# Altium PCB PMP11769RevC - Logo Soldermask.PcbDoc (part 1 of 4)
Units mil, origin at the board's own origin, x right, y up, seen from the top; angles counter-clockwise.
Board outline 7800 x 8510 mil, 4 copper layers (Top, Inner Top, Inner Bottom, Bottom), stack 33.235 mil thick; 451 components, 226 nets, 1199 pads, 1742 vias.
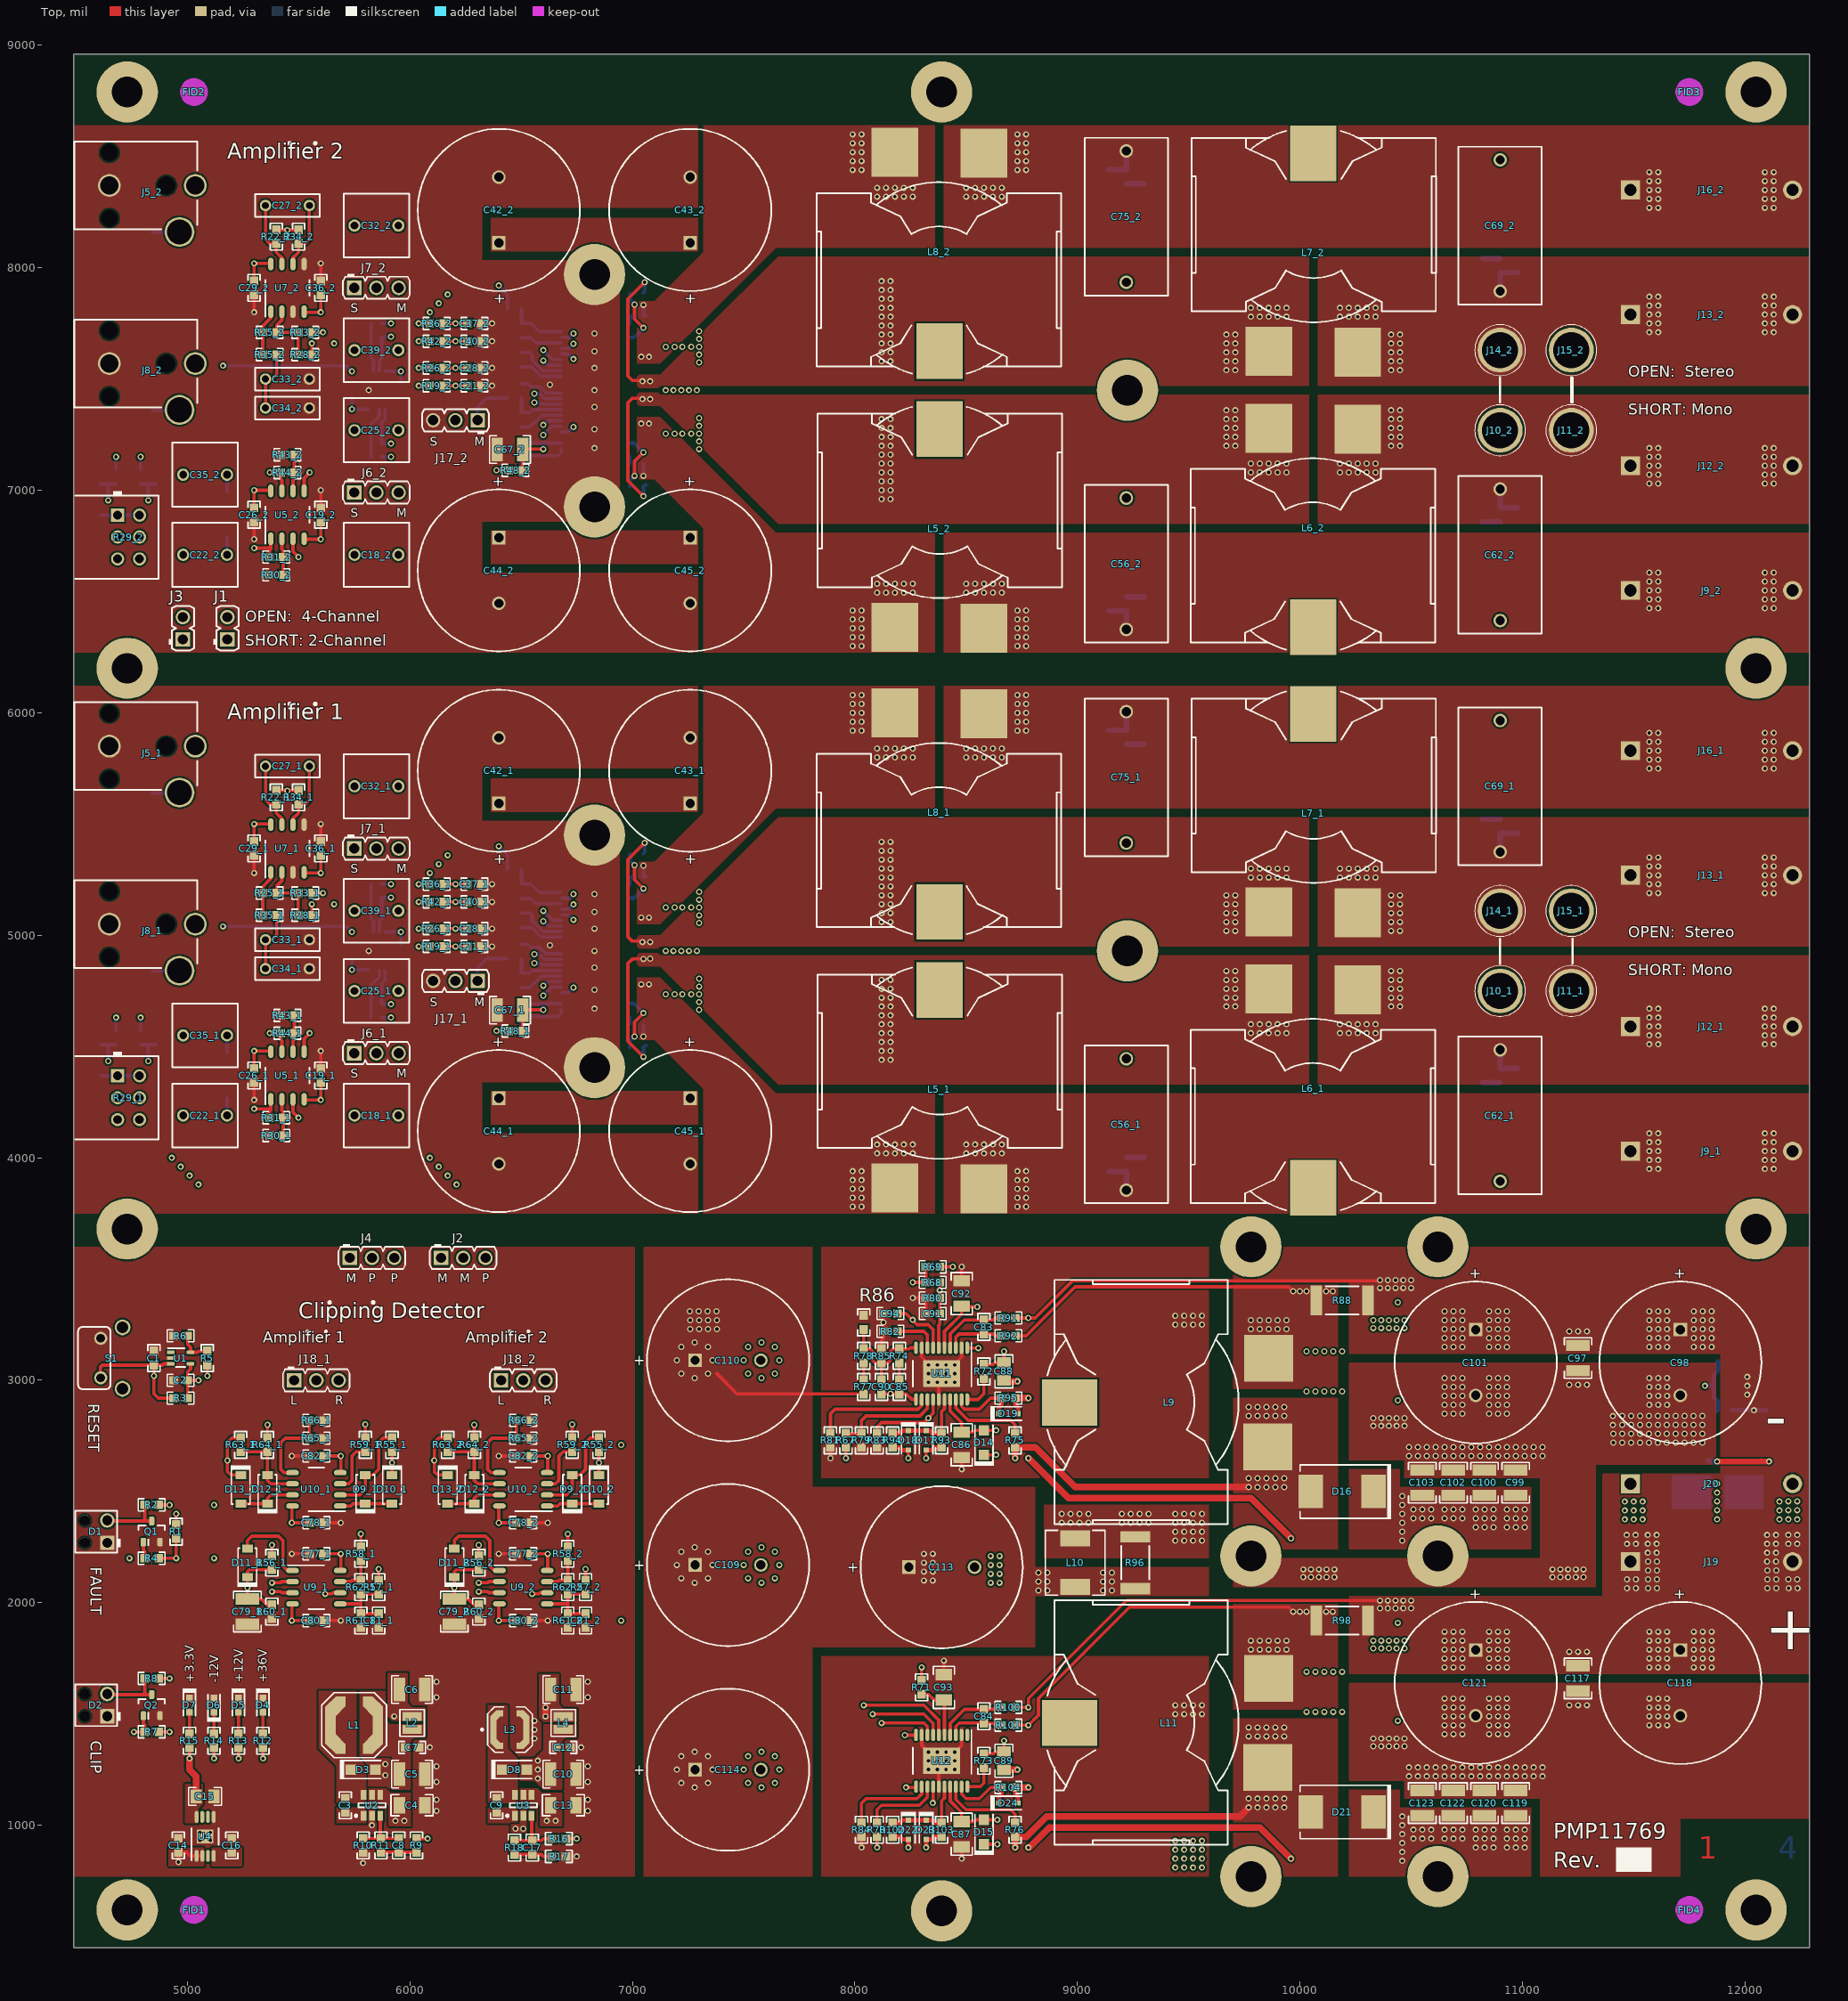
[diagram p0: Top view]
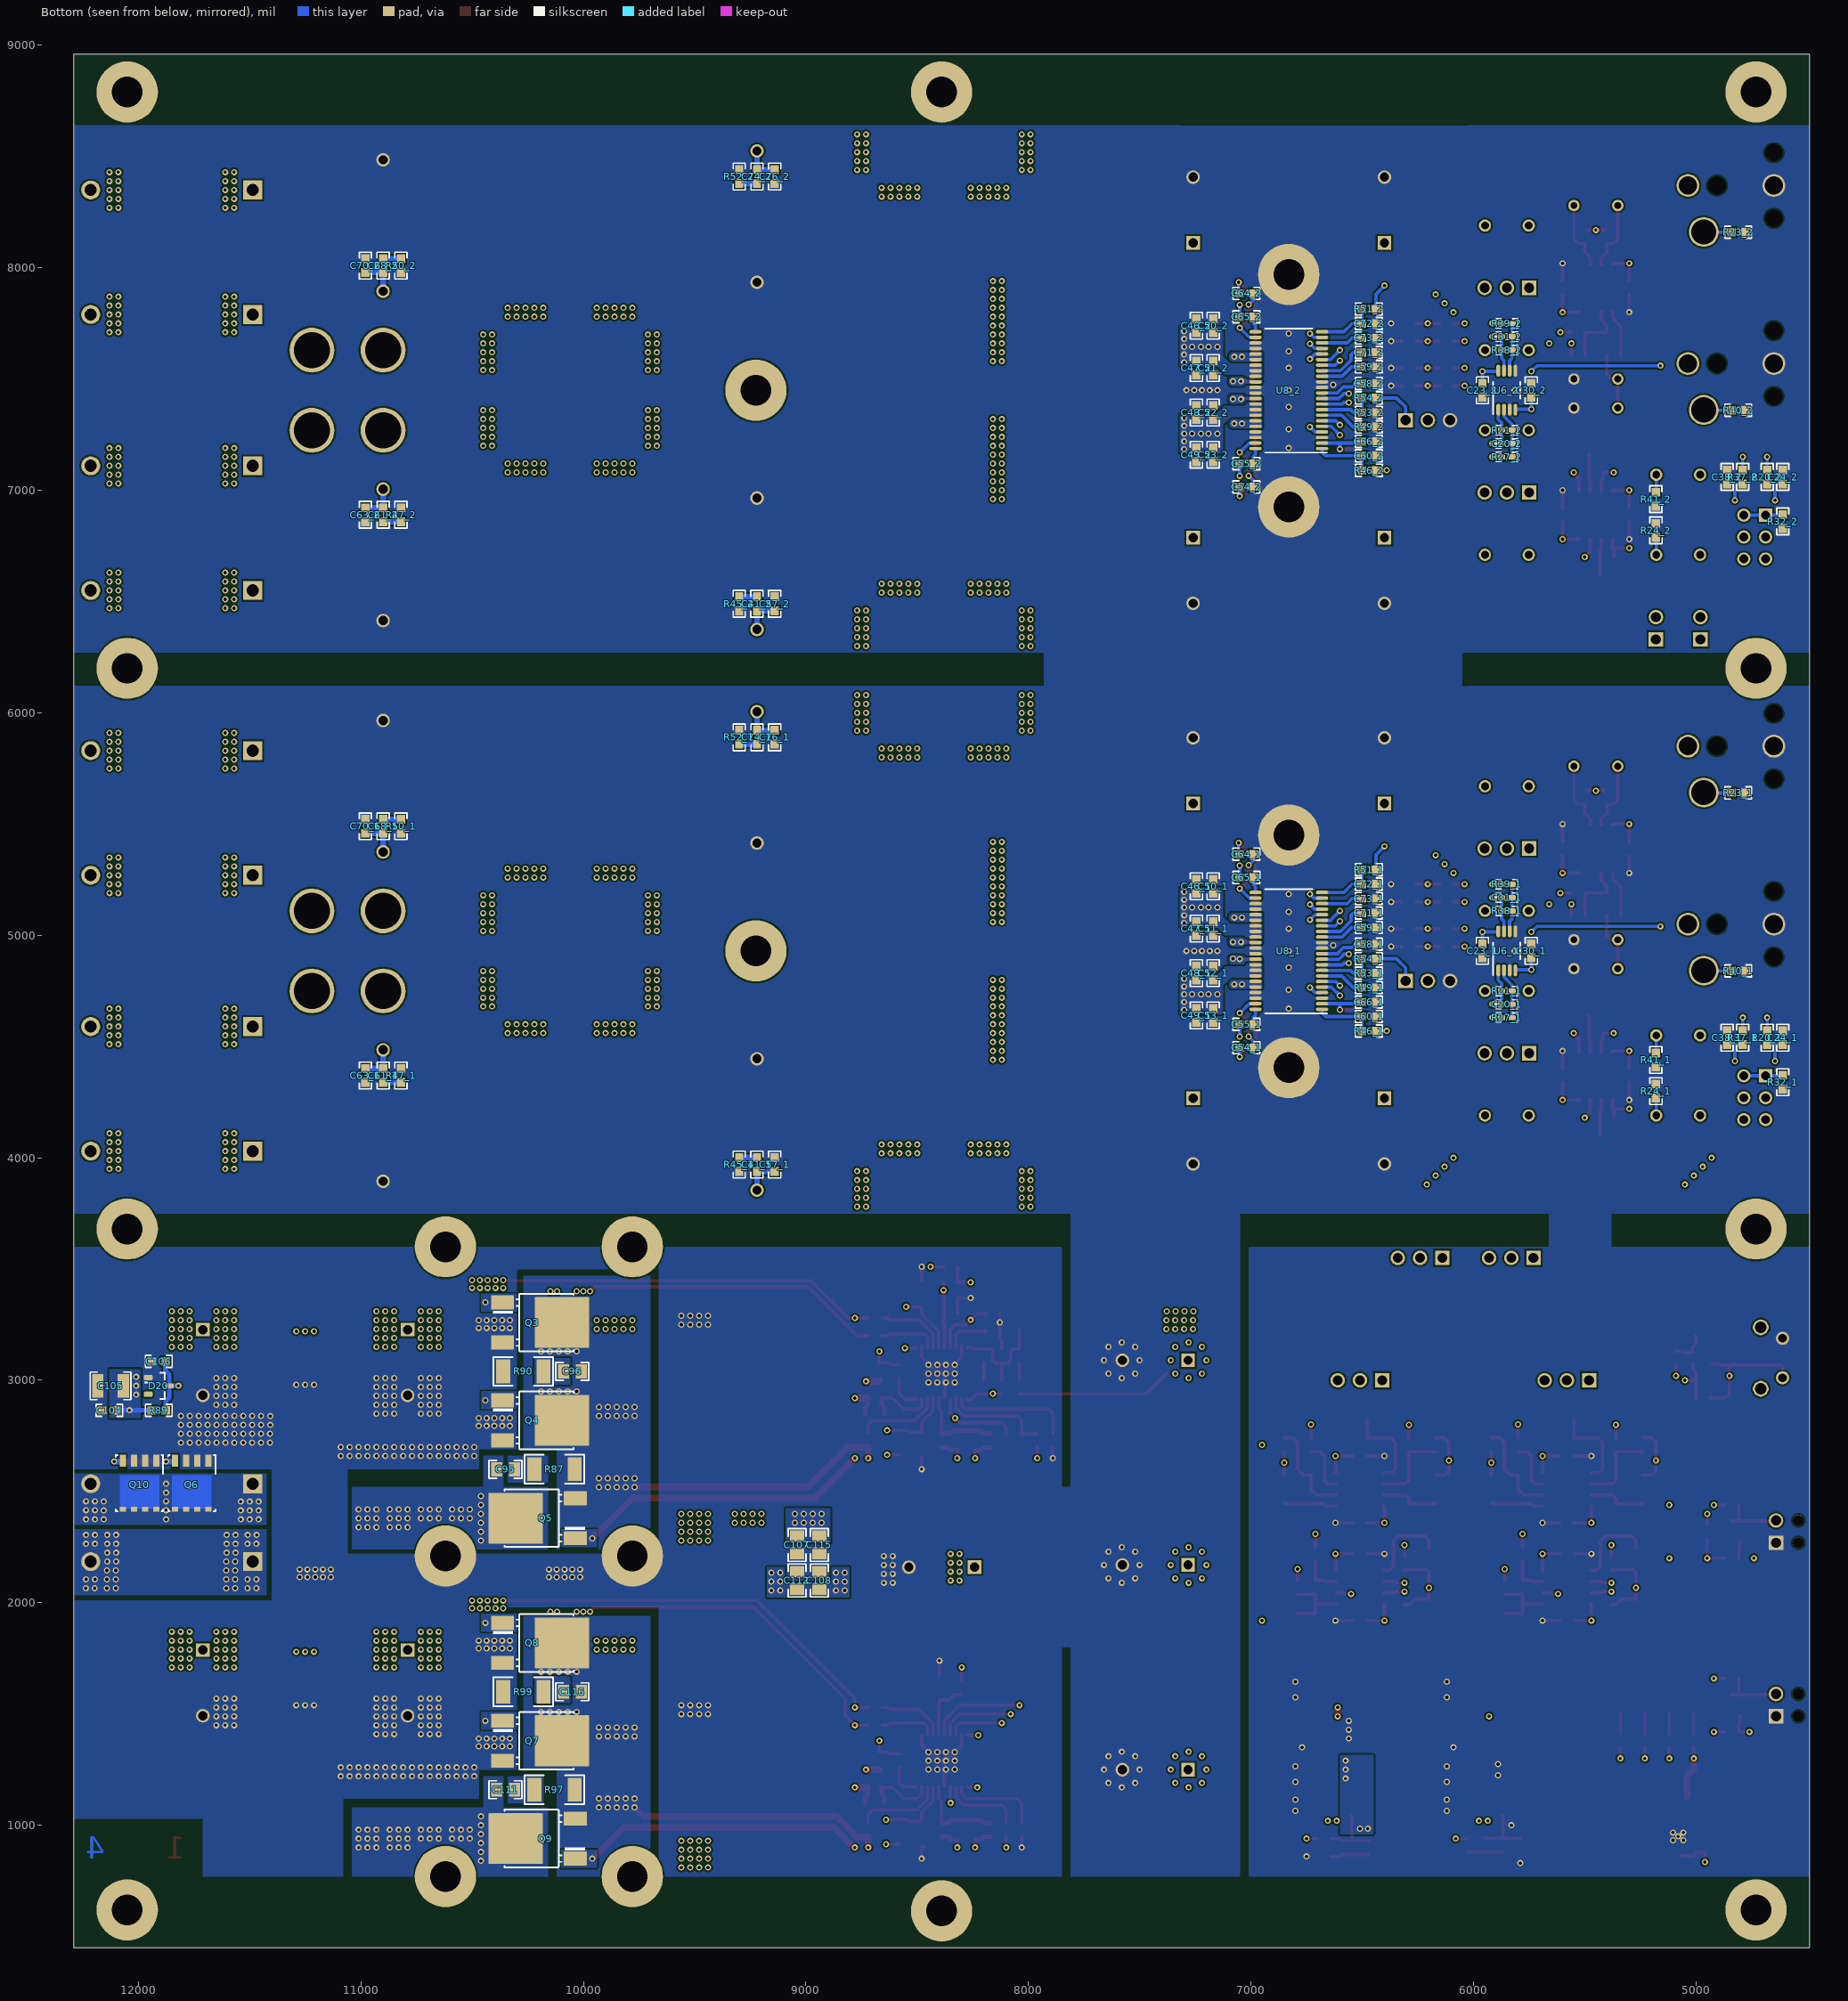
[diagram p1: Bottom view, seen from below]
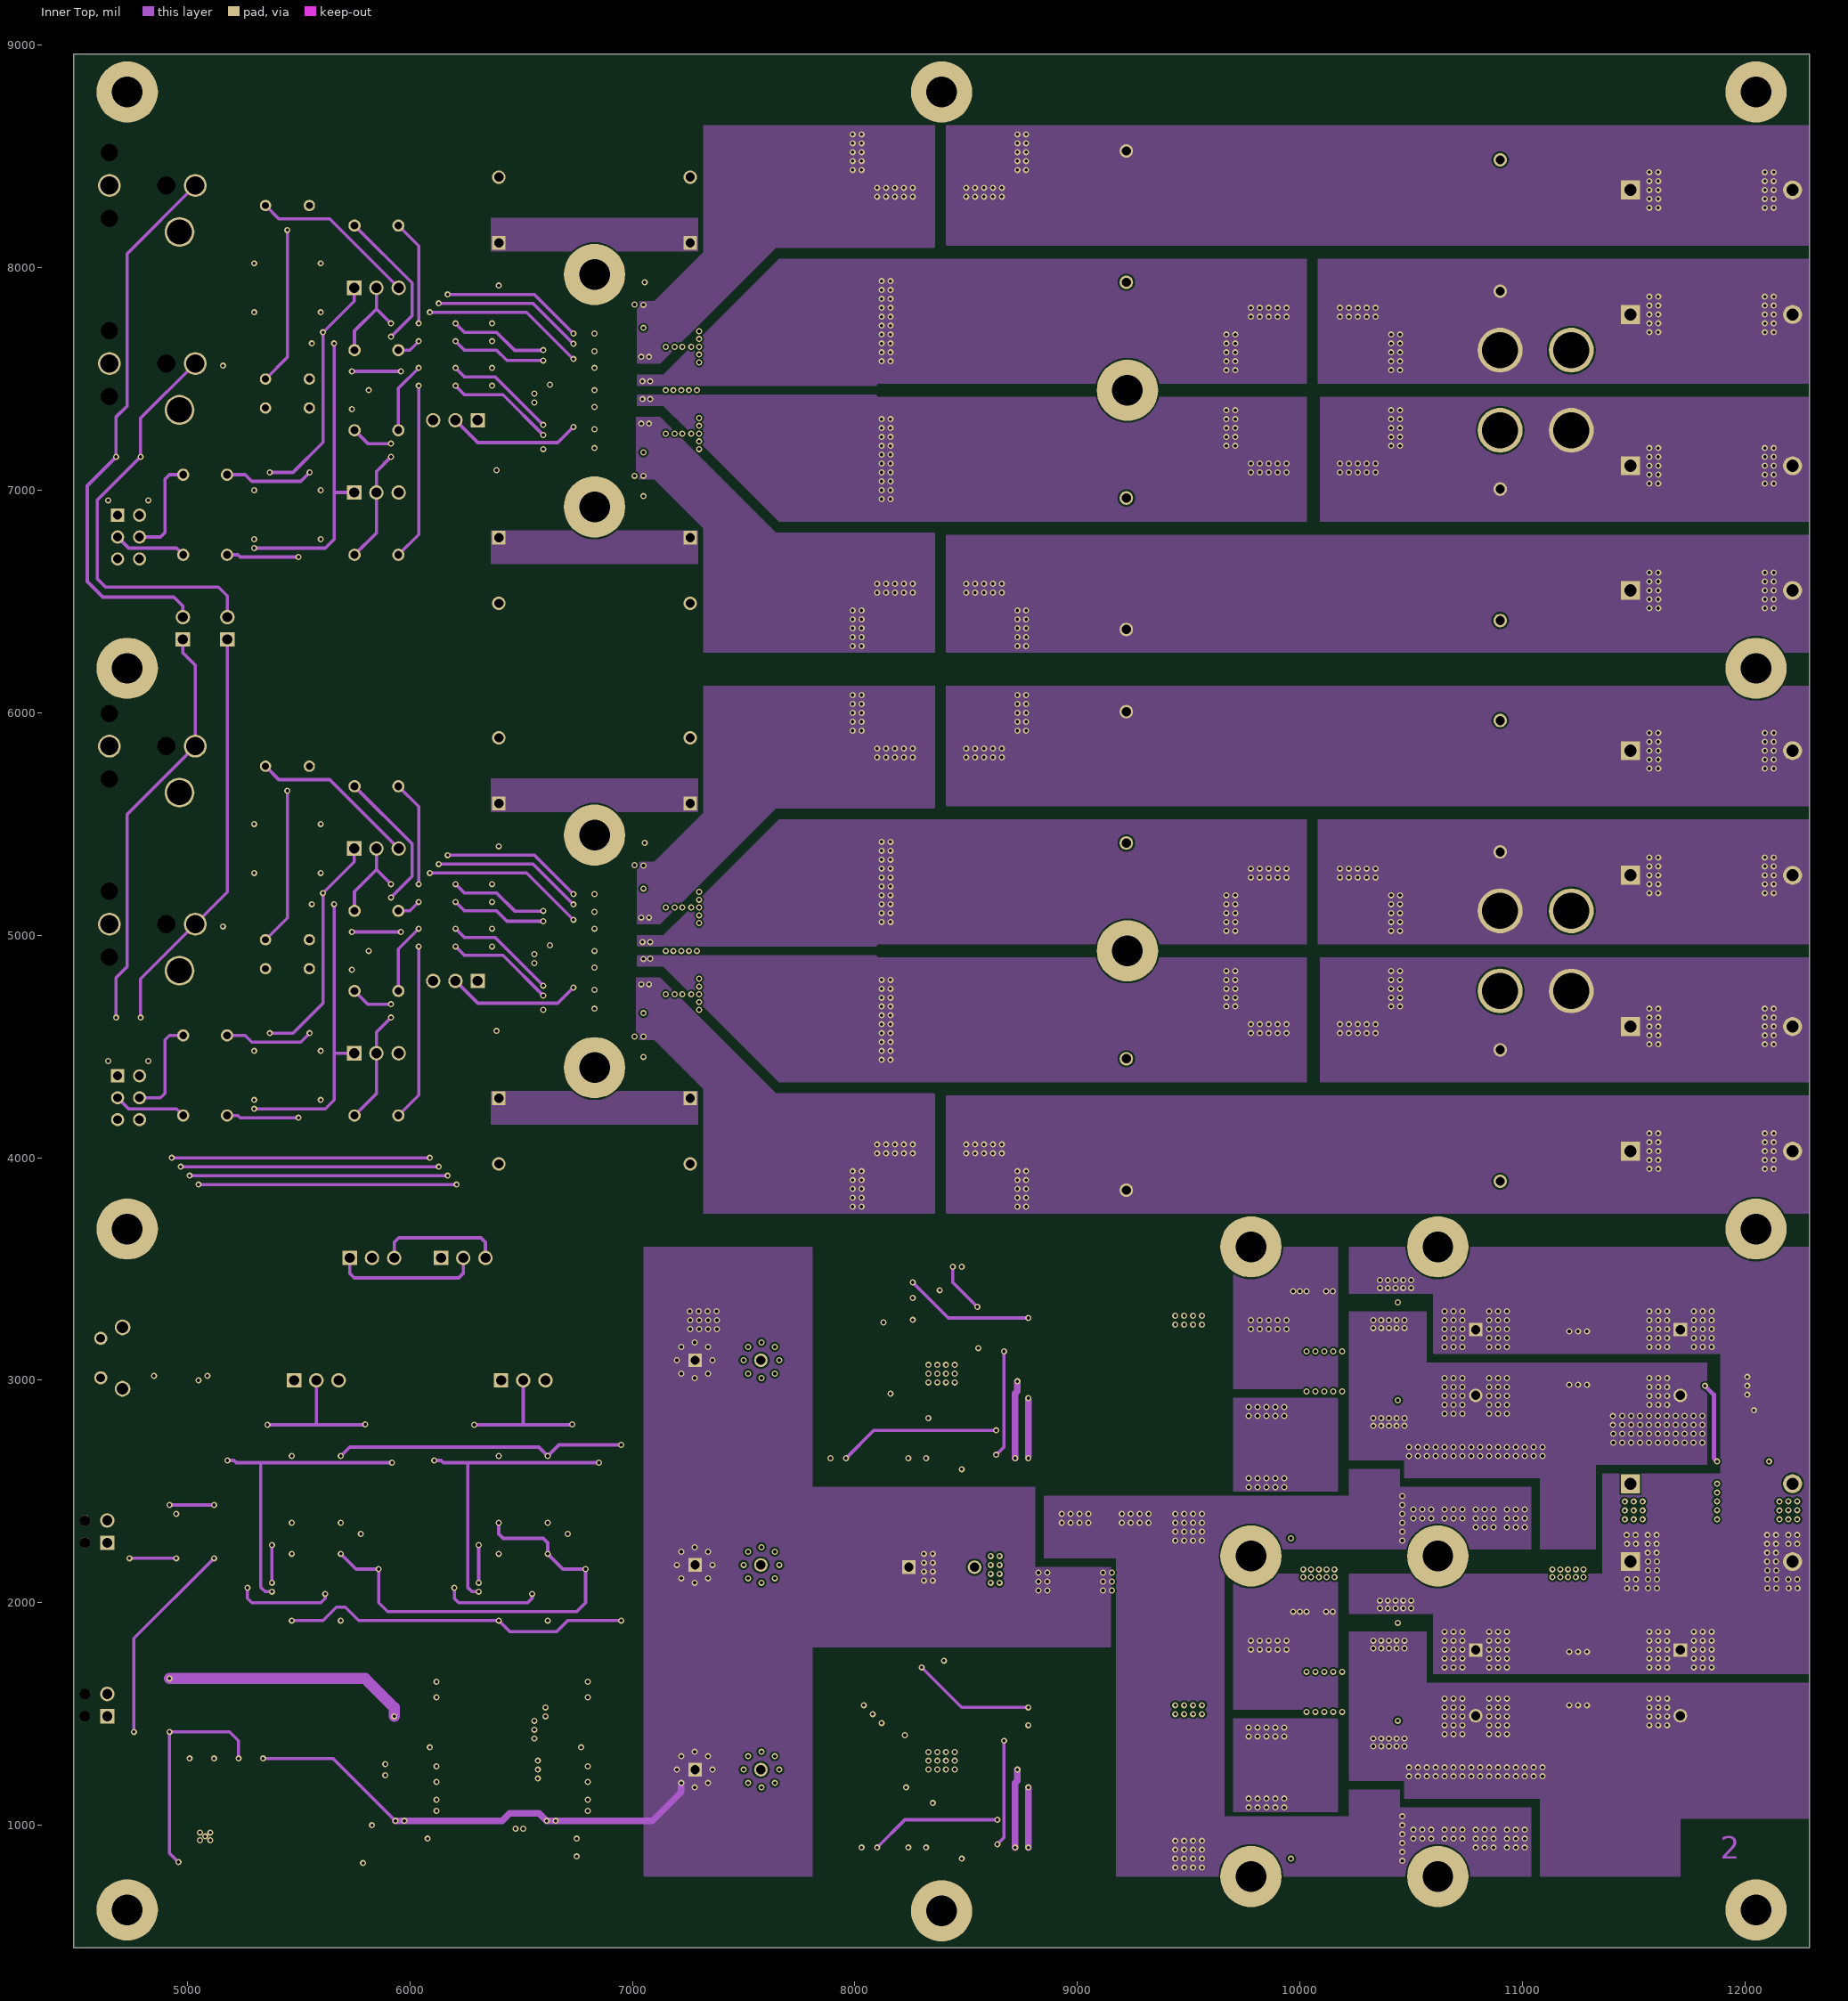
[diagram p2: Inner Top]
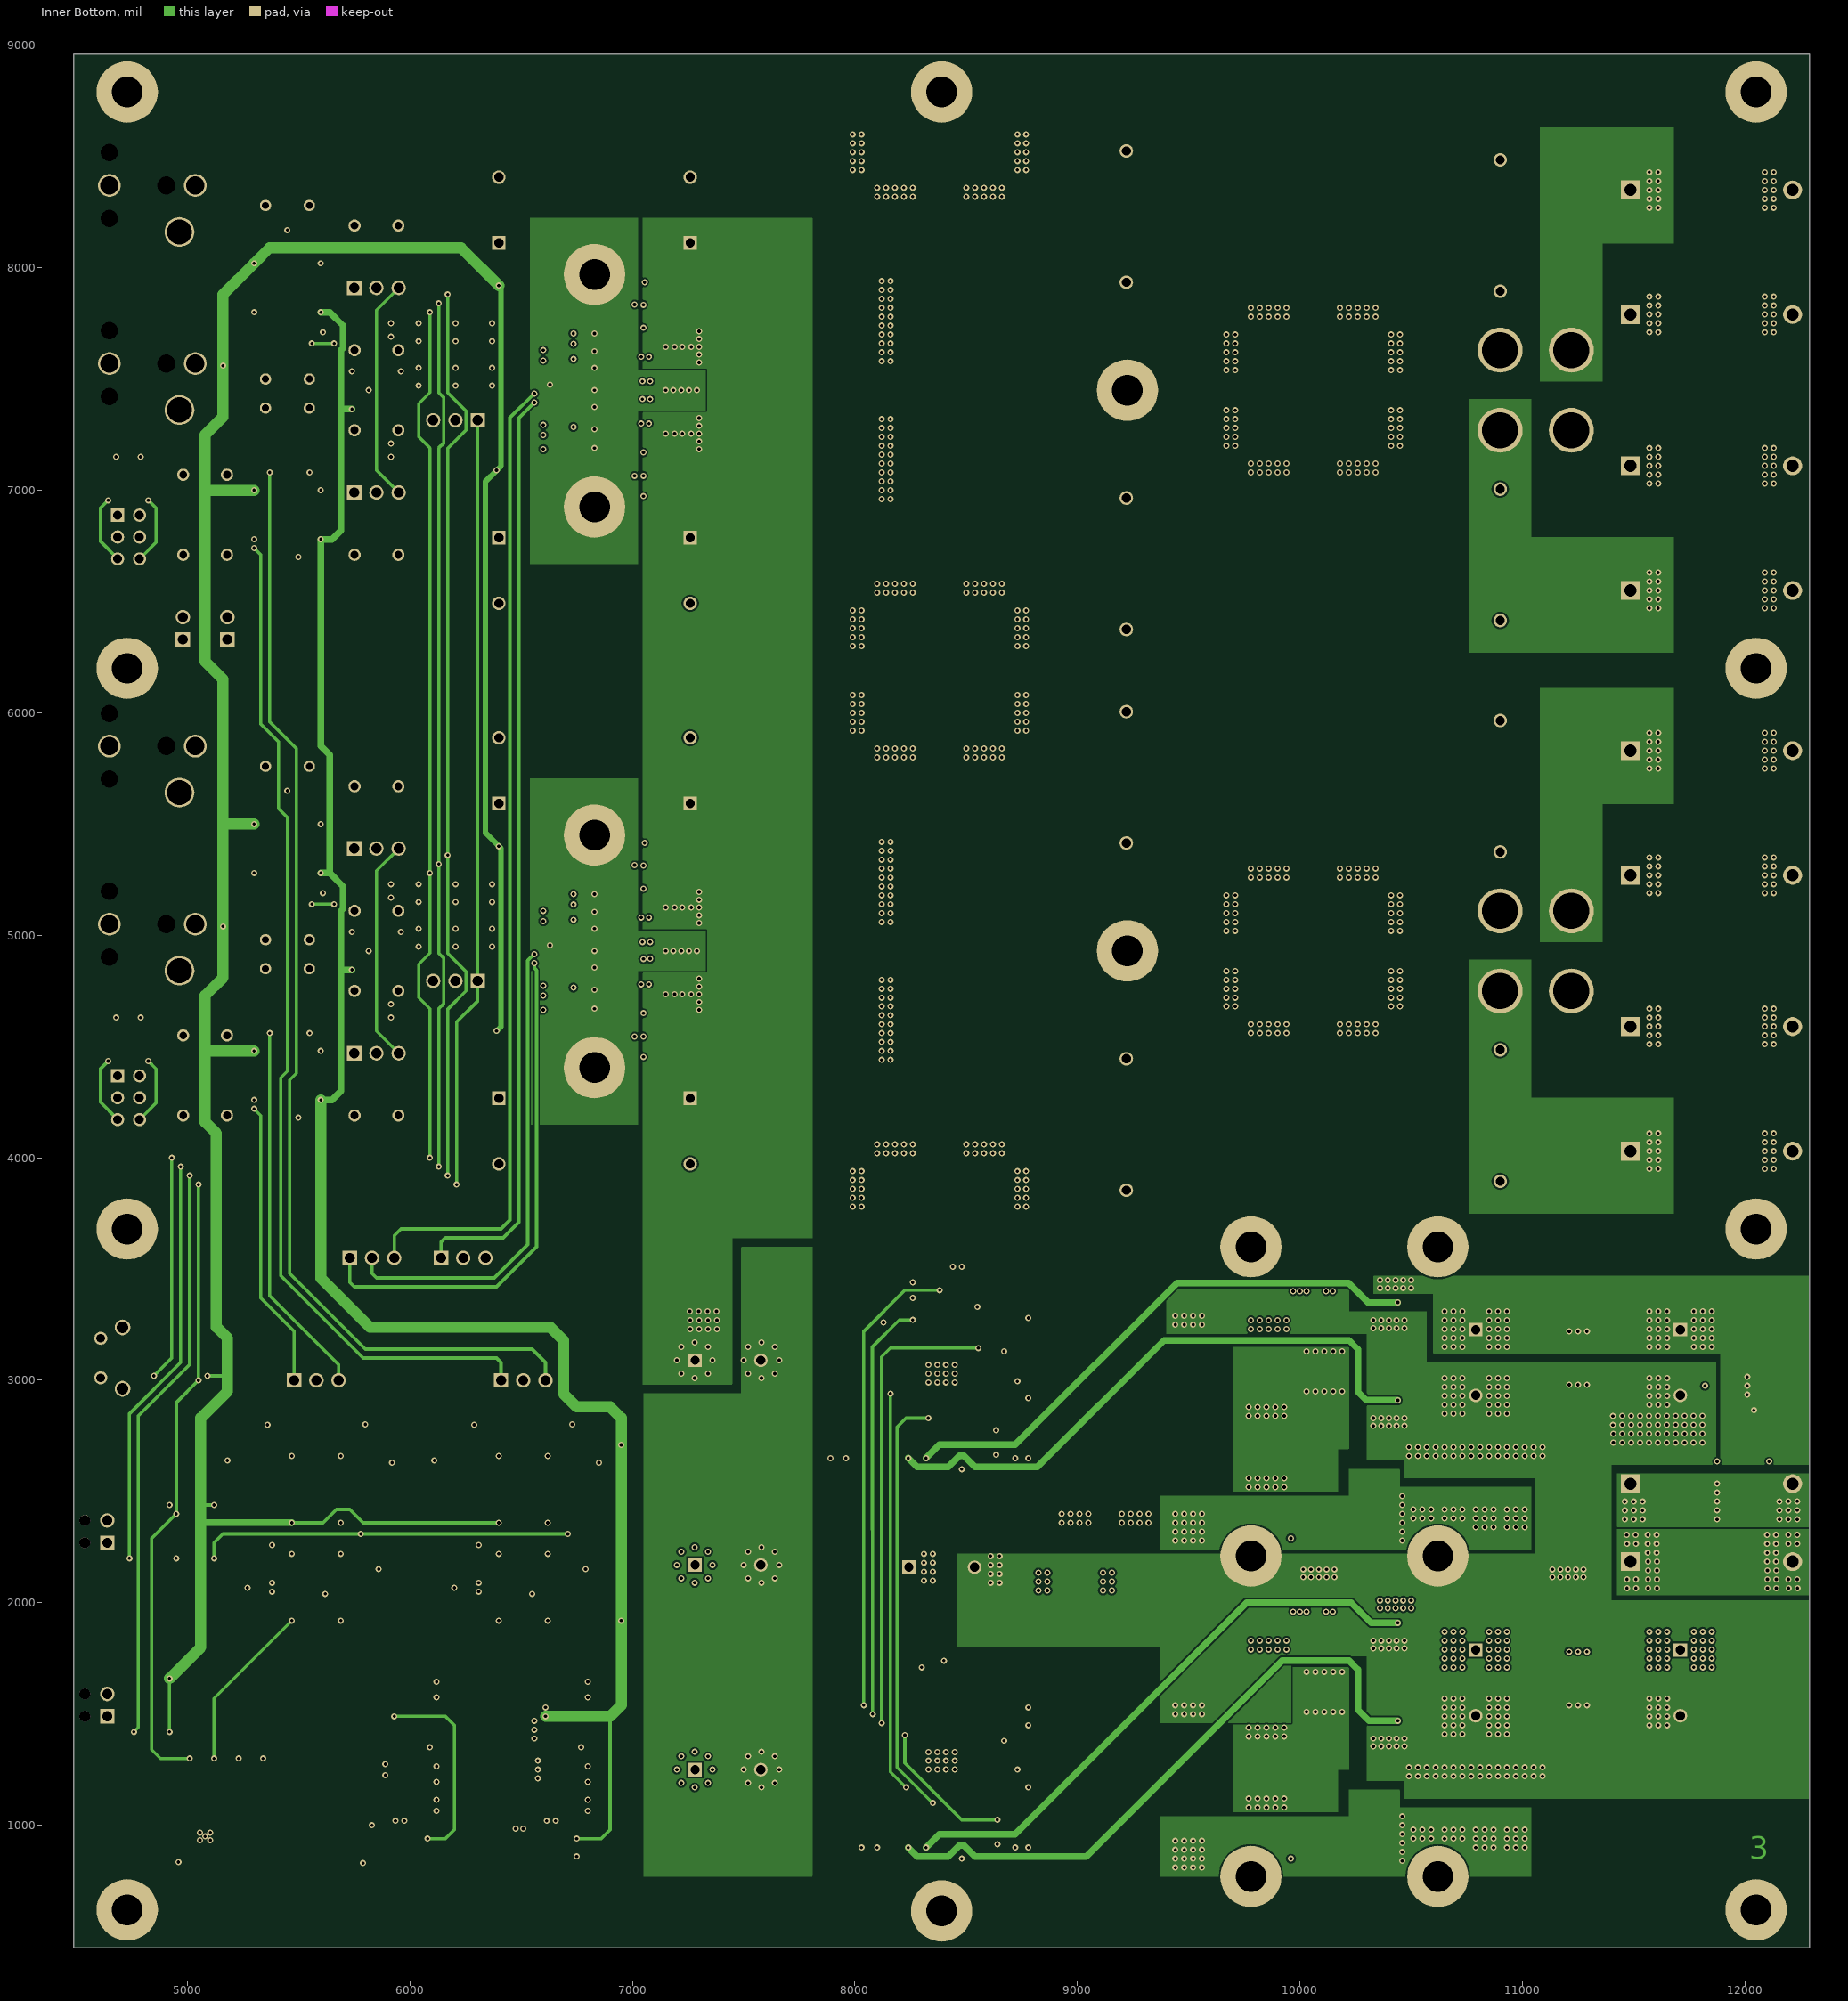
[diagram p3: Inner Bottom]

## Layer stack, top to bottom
Top Solder: solder mask 0.4, Solder Resist, Dk 3.5
Top: signal copper 1.4
Dielectric 1: core 12.6, FR-4, Dk 4.8
Inner Top: signal copper 1.4173
Dielectric 3: prepreg 5, Dk 4.2
Inner Bottom: signal copper 1.4173
Dielectric 2: core 10, Dk 4.2
Bottom: signal copper 1.4
Bottom Solder: solder mask 0.4, Solder Resist, Dk 3.5

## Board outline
4490,450 4490,8960 12290,8960 12290,450

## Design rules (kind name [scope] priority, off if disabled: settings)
Clearance [All] p1: gap=7.87
ComponentClearance [All] p1: gap=10 collisioncheckmode=3 verticalgap=10 showdistances=TRUE
DiffPairsRouting [All] p1: maxlimit=393.7 minlimit=4.92 mostfreqgap=5.91 toplayer_minwidth=15 toplayer_maxwidth=15 toplayer_prefwidth=15 midlayer1_minwidth=15 midlayer1_maxwidth=15 midlayer1_prefwidth=15 midlayer2_minwidth=15 midlayer2_maxwidth=15 midlayer2_prefwidth=15 bottomlayer_minwidth=15 bottomlayer_maxwidth=15 bottomlayer_prefwidth=15 maxuncoupledlength=500
FabricationTestPointUsage FabricationTestPointUsage_1 [All] p1: valid=0 allowmultiple=FALSE
FabricationTestpoint FabricationTestpoint_1 [All] p1: side=3 testpointundercomponent=TRUE minsize=40 maxsize=100 preferedsize=60 minholesize=0 maxholesize=40 preferedholesize=32 testpointgrid=1 allowsidetop=TRUE allowsidebottom=TRUE usegrid=TRUE gridtolerance=0.01
Height [All] p1: minheight=0 maxheight=1000.79 prefheight=500
HoleSize [All] p1: absolutevalues=TRUE maxlimit=236.22 minlimit=11.81 maxpercent=80.000 minpercent=20.000
HoleSize FabricationTestpoint [All] p2 off: absolutevalues=TRUE maxlimit=100 minlimit=1 maxpercent=80.000 minpercent=20.000
HoleSize FabricationTestPointUsage [All] p3 off: absolutevalues=TRUE maxlimit=100 minlimit=1 maxpercent=80.000 minpercent=20.000
MinimumAnnularRing [All] p1: minimumring=5.91
MinimumSolderMaskSliver [All] p1: minsoldermaskwidth=1
PlaneClearance [All] p1: clearance=19.68
PlaneConnect [All] p1: planeconnectstyle=Direct reliefexpansion=15.75 reliefentries=4 reliefconductorwidth=5.91 reliefairgap=5.91
PolygonConnect [All] p1: connectstyle=Direct reliefconductorwidth=5.91 reliefentries=4 polygonreliefangle="90 Angle" airgapwidth=10
RoomDefinition 2 [InComponentClass('2')] p1: confinementstyle=ConfineIn formatcopy=TRUE lockcomponents=FALSE outline 3880,6250 12335,6250 12335,8660 3880,8660
RoomDefinition 1 [InComponentClass('1')] p2: confinementstyle=ConfineIn formatcopy=TRUE lockcomponents=FALSE outline 3880,3730 12335,3730 12335,6140 3880,6140
RoutingCorners [All] p1: cornerstyle=45-Degree minsetback=49.21 maxsetback=49.21
RoutingVias [All] p1: holewidth=11.81 width=27.56 viastyle="Through Hole" minholewidth=11.81 minwidth=19.68 maxholewidth=39.37 maxwidth=59.06
SilkToSilkClearance [All] p1: silktosilkclearance=3.94
SilkToSolderMaskClearance SilkscreenOverComponentPads [IsPad] p1: minsilkscreentomaskgap=5 clearancetoexposedcopper=TRUE
SolderMaskExpansion [All] p1: expansion=2.95
UnpouredPolygon [All] p1: allowunpoured=FALSE
Width [All] p1: maxlimit=393.7 minlimit=4.92 preferedwidth=10 toplayer_minwidth=5.91 midlayer1_prefwidth=5.91 midlayer2_prefwidth=5.91 bottomlayer_minwidth=5.91 minimp=50.000000 maximp=50.000000 favimp=50.000000
17 further rules are at their usual default settings.

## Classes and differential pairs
channel class "PMP11769Revc - Clipping Detector": 1 2
channel class "PMP11769RevC - Amplifier": 1 2
net class OSC_IOP[1..2]: OSC_IOP1 OSC_IOP2
net class OSC_IOM[1..2]: OSC_IOM1 OSC_IOM2
net class IN_R[1..2]: IN_R1 IN_R2
net class IN_L[1..2]: IN_L1 IN_L2
component class 2: C18_2 C19_2 C20_2 C21_2 C22_2 C23_2 C24_2 C25_2 C26_2 C27_2 C28_2 C29_2 C30_2 C31_2 C32_2 C33_2 C34_2 C35_2 C36_2 C37_2 C38_2 C39_2 C40_2 C41_2 C42_2 C43_2 C44_2 C45_2 C46_2 C47_2 C48_2 C49_2 C50_2 C51_2 C52_2 C53_2 C54_2 C55_2 C56_2 C57_2 C58_2 C59_2 C60_2 C61_2 C62_2 C63_2 C64_2 C65_2 C66_2 C67_2 C68_2 C69_2 C70_2 C71_2 C72_2 C73_2 C74_2 C75_2 C76_2 J5_2 J6_2 J7_2 J8_2 J9_2 J10_2 J11_2 J12_2 J13_2 J14_2 J15_2 J16_2 J17_2 L5_2 L6_2 L7_2 L8_2 R19_2 R20_2 R21_2 R22_2 R23_2 R24_2 R25_2 R26_2 R27_2 R28_2 R29_2 R30_2 R31_2 R32_2 R33_2 R34_2 R35_2 R36_2 R37_2 R38_2 R39_2 R40_2 R41_2 R42_2 R43_2 R44_2 R45_2 R46_2 R47_2 R48_2 R49_2 R50_2 R51_2 R52_2 R53_2 R54_2 U5_2 U6_2 U7_2 U8_2
component class 1: C18_1 C19_1 C20_1 C21_1 C22_1 C23_1 C24_1 C25_1 C26_1 C27_1 C28_1 C29_1 C30_1 C31_1 C32_1 C33_1 C34_1 C35_1 C36_1 C37_1 C38_1 C39_1 C40_1 C41_1 C42_1 C43_1 C44_1 C45_1 C46_1 C47_1 C48_1 C49_1 C50_1 C51_1 C52_1 C53_1 C54_1 C55_1 C56_1 C57_1 C58_1 C59_1 C60_1 C61_1 C62_1 C63_1 C64_1 C65_1 C66_1 C67_1 C68_1 C69_1 C70_1 C71_1 C72_1 C73_1 C74_1 C75_1 C76_1 J5_1 J6_1 J7_1 J8_1 J9_1 J10_1 J11_1 J12_1 J13_1 J14_1 J15_1 J16_1 J17_1 L5_1 L6_1 L7_1 L8_1 R19_1 R20_1 R21_1 R22_1 R23_1 R24_1 R25_1 R26_1 R27_1 R28_1 R29_1 R30_1 R31_1 R32_1 R33_1 R34_1 R35_1 R36_1 R37_1 R38_1 R39_1 R40_1 R41_1 R42_1 R43_1 R44_1 R45_1 R46_1 R47_1 R48_1 R49_1 R50_1 R51_1 R52_1 R53_1 R54_1 U5_1 U6_1 U7_1 U8_1
net class BUFF_L[1..2]: BUFF_L1 BUFF_L2
net class BUFF_R[1..2]: BUFF_R1 BUFF_R2

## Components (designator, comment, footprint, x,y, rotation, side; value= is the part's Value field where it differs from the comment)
C1 "C1608X7R1E105K080AB" 0603 4850,3100 r90 top
C2 "C1608X7R1H104K" 0603 4970,3000 r0 top
C3 "C1608X7R1H104K" 0603 5710,1090 r270 top
C4 "C3216X7R1H105K" 1206 6010,1090 r0 top
C5 "C3225X7R1E106M" 1210 6010,1230 r0 top
C6 "C3225X7R1E106M" 1210 6010,1610 r0 top
C7 "C1608X7R1H104K" 0603 6010,1350 r180 top
C8 "C1608C0G1H221J" 0603 5950,910 r90 top
C9 "C1608X7R1H104K" 0603 6390,1090 r270 top
C10 "C3225X7R1E106M" 1210 6690,1230 r180 top
C11 "C3225X7R1E106M" 1210 6690,1610 r180 top
C12 "C1608X7R1H104K" 0603 6690,1350 r0 top
C13 "C3216X7R1H105K" 1206 6690,1090 r0 top
C14 "C1608X7R1E105K080AB" 0603 4960,910 r90 top
C15 "C2012X7R1A475M" 0805_HV 5080,1130 r0 top
C16 "C1608X7R1H102K" 0603 5200,910 r90 top
C17 "C1608C0G1H221J" 0603 6550,900 r90 top
C18_1 "R82CC4470Z330J" R82_720x720x1300 5850,4190 r180 top (schematic designator C18)
C18_2 "R82CC4470Z330J" R82_720x720x1300 5850,6710 r180 top (schematic designator C18)
C19_1 "C1608X7R1H104K" 0603 5600,4370 r90 top (schematic designator C19)
C19_2 "C1608X7R1H104K" 0603 5600,6890 r90 top (schematic designator C19)
C20_1 "C1005C0G1H220J050BA" 0402 5850,4690 r180 bottom (schematic designator C20)
C20_2 "C1005C0G1H220J050BA" 0402 5850,7210 r180 bottom (schematic designator C20)
C21_1 "C1608C0G1H101J" 0603 6290,4950 r0 top (schematic designator C21)
C21_2 "C1608C0G1H101J" 0603 6290,7470 r0 top (schematic designator C21)
C22_1 "R82CC4470Z330J" R82_720x720x1300 5080,4190 r180 top (schematic designator C22)
C22_2 "R82CC4470Z330J" R82_720x720x1300 5080,6710 r180 top (schematic designator C22)
C23_1 "C1608X7R1H104K" 0603 5960,4930 r270 bottom (schematic designator C23)
C23_2 "C1608X7R1H104K" 0603 5960,7450 r270 bottom (schematic designator C23)
C24_1 "C1608C0G1H101J" 0603 4610,4540 r90 bottom (schematic designator C24)
C24_2 "C1608C0G1H101J" 0603 4610,7060 r90 bottom (schematic designator C24)
C25_1 "R82CC4470Z330J" R82_720x720x1300 5850,4750 r180 top (schematic designator C25)
C25_2 "R82CC4470Z330J" R82_720x720x1300 5850,7270 r180 top (schematic designator C25)
C26_1 "C1608X7R1H104K" 0603 5300,4370 r270 top (schematic designator C26)
C26_2 "C1608X7R1H104K" 0603 5300,6890 r270 top (schematic designator C26)
C27_1 "R82DC3100DQ50J" R82_720x250x650 5450,5760 r0 top (schematic designator C27)
C27_2 "R82DC3100DQ50J" R82_720x250x650 5450,8280 r0 top (schematic designator C27)
C28_1 "C1608C0G1H101J" 0603 6290,5030 r0 top (schematic designator C28)
C28_2 "C1608C0G1H101J" 0603 6290,7550 r0 top (schematic designator C28)
C29_1 "C1608X7R1H104K" 0603 5300,5390 r270 top (schematic designator C29)
C29_2 "C1608X7R1H104K" 0603 5300,7910 r270 top (schematic designator C29)
C30_1 "C1608X7R1H104K" 0603 5740,4930 r90 bottom (schematic designator C30)
C30_2 "C1608X7R1H104K" 0603 5740,7450 r90 bottom (schematic designator C30)
C31_1 "C1005C0G1H220J050BA" 0402 5850,5170 r180 bottom (schematic designator C31)
C31_2 "C1005C0G1H220J050BA" 0402 5850,7690 r180 bottom (schematic designator C31)
C32_1 "R82CC4470Z330J" R82_720x720x1300 5850,5670 r180 top (schematic designator C32)
C32_2 "R82CC4470Z330J" R82_720x720x1300 5850,8190 r180 top (schematic designator C32)
C33_1 "R82DC3220DQ60J" R82_720x250x650 5450,4980 r0 top (schematic designator C33)
C33_2 "R82DC3220DQ60J" R82_720x250x650 5450,7500 r0 top (schematic designator C33)
C34_1 "R82DC3150AA60J" R82_720x250x650 5450,4850 r0 top (schematic designator C34)
C34_2 "R82DC3150AA60J" R82_720x250x650 5450,7370 r0 top (schematic designator C34)
C35_1 "R82CC4470Z330J" R82_720x720x1300 5080,4550 r180 top (schematic designator C35)
C35_2 "R82CC4470Z330J" R82_720x720x1300 5080,7070 r180 top (schematic designator C35)
C36_1 "C1608X7R1H104K" 0603 5600,5390 r90 top (schematic designator C36)
C36_2 "C1608X7R1H104K" 0603 5600,7910 r90 top (schematic designator C36)
C37_1 "C1608C0G1H101J" 0603 6290,5230 r0 top (schematic designator C37)
C37_2 "C1608C0G1H101J" 0603 6290,7750 r0 top (schematic designator C37)
C38_1 "C1608C0G1H101J" 0603 4860,4540 r90 bottom (schematic designator C38)
C38_2 "C1608C0G1H101J" 0603 4860,7060 r90 bottom (schematic designator C38)
C39_1 "R82CC4470Z330J" R82_720x720x1300 5850,5110 r180 top (schematic designator C39)
C39_2 "R82CC4470Z330J" R82_720x720x1300 5850,7630 r180 top (schematic designator C39)
C40_1 "C1608C0G1H101J" 0603 6290,5150 r0 top (schematic designator C40)
C40_2 "C1608C0G1H101J" 0603 6290,7670 r0 top (schematic designator C40)
C41_1 "C1608X7R1H103K" 0603 9220,3970 r90 bottom (schematic designator C41)
C41_2 "C1608X7R1H103K" 0603 9220,6490 r90 bottom (schematic designator C41)
C42_1 "UPW1H821MHD6" PW_1800x2000 6400,5740 r90 top (schematic designator C42)
C42_2 "UPW1H821MHD6" PW_1800x2000 6400,8260 r90 top (schematic designator C42)
C43_1 "UPW1H821MHD6" PW_1800x2000 7260,5740 r90 top (schematic designator C43)
C43_2 "UPW1H821MHD6" PW_1800x2000 7260,8260 r90 top (schematic designator C43)
C44_1 "UPW1H821MHD6" PW_1800x2000 6400,4120 r270 top (schematic designator C44)
C44_2 "UPW1H821MHD6" PW_1800x2000 6400,6640 r270 top (schematic designator C44)
C45_1 "UPW1H821MHD6" PW_1800x2000 7260,4120 r270 top (schematic designator C45)
C45_2 "UPW1H821MHD6" PW_1800x2000 7260,6640 r270 top (schematic designator C45)
C46_1 "UMK107AB7105KA-T" 0603 7245,5220 r90 bottom (schematic designator C46)
C46_2 "UMK107AB7105KA-T" 0603 7245,7740 r90 bottom (schematic designator C46)
C47_1 "UMK107AB7105KA-T" 0603 7245,5030 r270 bottom (schematic designator C47)
C47_2 "UMK107AB7105KA-T" 0603 7245,7550 r270 bottom (schematic designator C47)
C48_1 "UMK107AB7105KA-T" 0603 7245,4830 r90 bottom (schematic designator C48)
C48_2 "UMK107AB7105KA-T" 0603 7245,7350 r90 bottom (schematic designator C48)
C49_1 "UMK107AB7105KA-T" 0603 7245,4640 r270 bottom (schematic designator C49)
C49_2 "UMK107AB7105KA-T" 0603 7245,7160 r270 bottom (schematic designator C49)
C50_1 "UMK107AB7105KA-T" 0603 7170,5220 r90 bottom (schematic designator C50)
C50_2 "UMK107AB7105KA-T" 0603 7170,7740 r90 bottom (schematic designator C50)
C51_1 "UMK107AB7105KA-T" 0603 7170,5030 r270 bottom (schematic designator C51)
C51_2 "UMK107AB7105KA-T" 0603 7170,7550 r270 bottom (schematic designator C51)
C52_1 "UMK107AB7105KA-T" 0603 7170,4830 r90 bottom (schematic designator C52)
C52_2 "UMK107AB7105KA-T" 0603 7170,7350 r90 bottom (schematic designator C52)
C53_1 "UMK107AB7105KA-T" 0603 7170,4640 r270 bottom (schematic designator C53)
C53_2 "UMK107AB7105KA-T" 0603 7170,7160 r270 bottom (schematic designator C53)
C54_1 "GRM188R71H333KA61D" 0603 7020,4495 r0 bottom (schematic designator C54)
C54_2 "GRM188R71H333KA61D" 0603 7020,7015 r0 bottom (schematic designator C54)
C55_1 "GRM188R71H333KA61D" 0603 7020,4600 r0 bottom (schematic designator C55)
C55_2 "GRM188R71H333KA61D" 0603 7020,7120 r0 bottom (schematic designator C55)
C56_1 "PHE426HB7100JR06" PHE426_1800x950x1750 9220,4150 r90 top (schematic designator C56)
C56_2 "PHE426HB7100JR06" PHE426_1800x950x1750 9220,6670 r90 top (schematic designator C56)
C57_1 "C1608C0G2A102J" 0603 9140,3970 r90 bottom (schematic designator C57)
C57_2 "C1608C0G2A102J" 0603 9140,6490 r90 bottom (schematic designator C57)
C58_1 "C1608X7R1E105K080AB" 0603 6470,4960 r180 bottom (schematic designator C58)
C58_2 "C1608X7R1E105K080AB" 0603 6470,7480 r180 bottom (schematic designator C58)
C59_1 "C1608X7R1E105K080AB" 0603 6470,5035 r180 bottom (schematic designator C59)
C59_2 "C1608X7R1E105K080AB" 0603 6470,7555 r180 bottom (schematic designator C59)
C60_1 "C1608X7R1H104K" 0603 6470,4635 r0 bottom (schematic designator C60)
C60_2 "C1608X7R1H104K" 0603 6470,7155 r0 bottom (schematic designator C60)
C61_1 "C1608X7R1H103K" 0603 10900,4370 r270 bottom (schematic designator C61)
C61_2 "C1608X7R1H103K" 0603 10900,6890 r270 bottom (schematic designator C61)
C62_1 "PHE426HB7100JR06" PHE426_1800x950x1750 10900,4190 r270 top (schematic designator C62)
C62_2 "PHE426HB7100JR06" PHE426_1800x950x1750 10900,6710 r270 top (schematic designator C62)
C63_1 "C1608C0G2A102J" 0603 10980,4370 r270 bottom (schematic designator C63)
C63_2 "C1608C0G2A102J" 0603 10980,6890 r270 bottom (schematic designator C63)
C64_1 "GRM188R71H333KA61D" 0603 7020,5365 r180 bottom (schematic designator C64)
C64_2 "GRM188R71H333KA61D" 0603 7020,7885 r180 bottom (schematic designator C64)
C65_1 "GRM188R71H333KA61D" 0603 7020,5260 r180 bottom (schematic designator C65)
C65_2 "GRM188R71H333KA61D" 0603 7020,7780 r180 bottom (schematic designator C65)
C66_1 "C1608X7R1H104K" 0603 6470,4700 r0 bottom (schematic designator C66)
C66_2 "C1608X7R1H104K" 0603 6470,7220 r0 bottom (schematic designator C66)
C67_1 "C3225X7R1E106M" 1210 6450,4663.54 r180 top (schematic designator C67)
C67_2 "C3225X7R1E106M" 1210 6450,7183.54 r180 top (schematic designator C67)
C68_1 "C1608X7R1H103K" 0603 10900,5490 r90 bottom (schematic designator C68)
C68_2 "C1608X7R1H103K" 0603 10900,8010 r90 bottom (schematic designator C68)
C69_1 "PHE426HB7100JR06" PHE426_1800x950x1750 10900,5670 r90 top (schematic designator C69)
C69_2 "PHE426HB7100JR06" PHE426_1800x950x1750 10900,8190 r90 top (schematic designator C69)
C70_1 "C1608C0G2A102J" 0603 10980,5490 r90 bottom (schematic designator C70)
C70_2 "C1608C0G2A102J" 0603 10980,8010 r90 bottom (schematic designator C70)
C71_1 "C1608X7R1E105K080AB" 0603 6470,5100 r0 bottom (schematic designator C71)
C71_2 "C1608X7R1E105K080AB" 0603 6470,7620 r0 bottom (schematic designator C71)
C72_1 "C1608X7R1H104K" 0603 6470,5230 r0 bottom (schematic designator C72)
C72_2 "C1608X7R1H104K" 0603 6470,7750 r0 bottom (schematic designator C72)
C73_1 "C1608X7R1H104K" 0603 6470,5165 r180 bottom (schematic designator C73)
C73_2 "C1608X7R1H104K" 0603 6470,7685 r180 bottom (schematic designator C73)
C74_1 "C1608X7R1H103K" 0603 9220,5890 r270 bottom (schematic designator C74)
C74_2 "C1608X7R1H103K" 0603 9220,8410 r270 bottom (schematic designator C74)
C75_1 "PHE426HB7100JR06" PHE426_1800x950x1750 9220,5710 r270 top (schematic designator C75)
C75_2 "PHE426HB7100JR06" PHE426_1800x950x1750 9220,8230 r270 top (schematic designator C75)
C76_1 "C1608C0G2A102J" 0603 9140,5890 r270 bottom (schematic designator C76)
C76_2 "C1608C0G2A102J" 0603 9140,8410 r270 bottom (schematic designator C76)
C77_1 "C1608X7R1H104K" 0603 5580,2220 r180 top (schematic designator C77)
C77_2 "C1608X7R1H104K" 0603 6510,2220 r180 top (schematic designator C77)
C78_1 "C1608X7R1H104K" 0603 5580,2360 r0 top (schematic designator C78)
C78_2 "C1608X7R1H104K" 0603 6510,2360 r0 top (schematic designator C78)
C79_1 "C3225X7R1E106M" 1210 5270,1960 r270 top (schematic designator C79)
C79_2 "C3225X7R1E106M" 1210 6200,1960 r270 top (schematic designator C79)
C80_1 "C1608X7R1H104K" 0603 5580,1920 r0 top (schematic designator C80)
C80_2 "C1608X7R1H104K" 0603 6510,1920 r0 top (schematic designator C80)
C81_1 "C1608X7R1H104K" 0603 5860,1920 r90 top (schematic designator C81)
C81_2 "C1608X7R1H104K" 0603 6790,1920 r90 top (schematic designator C81)
C82_1 "C1608X7R1H104K" 0603 5580,2660 r180 top (schematic designator C82)
C82_2 "C1608X7R1H104K" 0603 6510,2660 r180 top (schematic designator C82)
C83 "C1608X7R1H221K" 0603 8580,3240 r270 top
C84 "C1608X7R1H221K" 0603 8580,1490 r270 top
C85 "C1608X7R1H473K" 0603 8200,2970 r90 top
C86 "C3216X7R1C475M" 1206 8480,2710 r270 top
C87 "C3216X7R1C475M" 1206 8480,960 r270 top
C88 "C2012X7R1E224K" 0805_HV 8670,3040 r270 top
C89 "C2012X7R1E224K" 0805_HV 8670,1290 r270 top
C90 "C1608X7R1H102K" 0603 8120,2970 r90 top
C91 "C1608C0G1H101J" 0603 8350,3300 r180 top
C92 "C3216X7R1H105K" 1206 8480,3390 r270 top
C93 "C3216X7R1H105K" 1206 8400,1620 r270 top
C94 "GCM188R70J225KE22D" 0603 8160,3300 r180 top
C95 "C2012X7R2A102M" 0805_HV 10350,2600 r0 bottom
C96 "C2012X7R2A102M" 0805_HV 10050,3040 r0 bottom
C97 "CGA6P3X7R1H475K250AB" 1210 11250,3100 r270 top
C98 "UPW1V182MHD6" PW_1800x2000 11710,3080 r270 top
C99 "CGA6P3X7R1H475K250AB" 1210 10970,2540 r90 top
C100 "CGA6P3X7R1H475K250AB" 1210 10830,2540 r90 top
C101 "UPW1V182MHD6" PW_1800x2000 10790,3080 r270 top
C102 "CGA6P3X7R1H475K250AB" 1210 10690,2540 r90 top
C103 "CGA6P3X7R1H475K250AB" 1210 10550,2540 r90 top
C104 "C1608X7R1H104K" 0603 12130,2865 r0 bottom
C105 "CGA6P3X7R1H475K250AB" 1210 12125,2975 r0 bottom
C106 "C1608X7R1H104K" 0603 11908.5,3085 r180 bottom
C107 "C2012X7R2A104K125AA" 0805_HV 9040,2260 r90 bottom
C108 "C2012X7R2A104K125AA" 0805_HV 8940,2100 r90 bottom
C109 "UPW1H821MHD6" PW_1800x2000 7430,2170 r0 top
C110 "UPW1H821MHD6" PW_1800x2000 7430,3090 r0 top
C111 "C2012X7R2A102M" 0805_HV 10350,1160 r0 bottom
C112 "C2012X7R2A102M" 0805_HV 9040,2100 r90 bottom
C113 "UPW1H821MHD6" PW_1800x2000 8390,2160 r0 top
C114 "UPW1H821MHD6" PW_1800x2000 7430,1250 r0 top
C115 "C2012X7R2A102M" 0805_HV 8940,2260 r90 bottom
C116 "C2012X7R2A102M" 0805_HV 10050,1600 r0 bottom
C117 "CGA6P3X7R1H475K250AB" 1210 11250,1660 r270 top
C118 "UPW1V182MHD6" PW_1800x2000 11710,1640 r270 top
C119 "CGA6P3X7R1H475K250AB" 1210 10970,1100 r90 top
C120 "CGA6P3X7R1H475K250AB" 1210 10830,1100 r90 top
C121 "UPW1V182MHD6" PW_1800x2000 10790,1640 r270 top
C122 "CGA6P3X7R1H475K250AB" 1210 10690,1100 r90 top
C123 "CGA6P3X7R1H475K250AB" 1210 10550,1100 r90 top
D1 "551-0303F" 551-0403_Red 4590,2320 r180 top
D2 "551-0303F" 551-0403_Red 4590,1540 r180 top
D3 "PMEG6010" SOD-123F 5790,1250 r0 top
D4 "150060GS75000" WL-SMCW_GREEN 5340,1540 r270 top
D5 "150060GS75000" WL-SMCW_GREEN 5230,1540 r270 top
D6 "150060GS75000" WL-SMCW_GREEN 5120,1540 r90 top
D7 "150060GS75000" WL-SMCW_GREEN 5010,1540 r270 top
D8 "PMEG6010" SOD-123F 6470,1250 r0 top
D9_1 "1N4148" SOD-123FL 5800,2510 r90 top (schematic designator D9)
D9_2 "1N4148" SOD-123FL 6730,2510 r90 top (schematic designator D9)
D10_1 "1N4148" SOD-123FL 5920,2510 r270 top (schematic designator D10)
D10_2 "1N4148" SOD-123FL 6850,2510 r270 top (schematic designator D10)
D11_1 "1N4148" SOD-123FL 5270,2180 r90 top (schematic designator D11)
D11_2 "1N4148" SOD-123FL 6200,2180 r90 top (schematic designator D11)
D12_1 "1N4148" SOD-123FL 5360,2510 r90 top (schematic designator D12)
D12_2 "1N4148" SOD-123FL 6290,2510 r90 top (schematic designator D12)
D13_1 "1N4148" SOD-123FL 5240,2510 r270 top (schematic designator D13)
D13_2 "1N4148" SOD-123FL 6170,2510 r270 top (schematic designator D13)
D14 "PMEG6010" SOD-123F 8580,2720 r90 top
D15 "PMEG6010" SOD-123F 8580,970 r90 top
D16 "SS63" SMC 10190,2500 r180 top
D17 "BAT54" sod-323 8320,2730 r270 top
D18 "BAT54" sod-323 8240,2730 r270 top
D19 "BAT54" sod-323 8690,2850 r0 top
D20 "BZX84C15LT1G" SOT-23 11908.5,2975 r180 bottom
D21 "SS63" SMC 10190,1060 r180 top
D22 "BAT54" sod-323 8240,980 r270 top
D23 "BAT54" sod-323 8320,980 r270 top
D24 "BAT54" sod-323 8690,1100 r0 top
FID1 "Fiducial" Fiducial10-30 5030,620 r0 top
FID2 "Fiducial" Fiducial10-30 5030,8790 r90 top
FID3 "Fiducial" Fiducial10-30 11750,8790 r90 top
FID4 "Fiducial" Fiducial10-30 11750,620 r90 top
J1 "61300211121" WURTH_61300211121 5180,6380 r90 top
J2 "61300311121" WURTH_61300311121 6240,3550 r0 top
J3 "61300211121" WURTH_61300211121 4980,6380 r90 top
J4 "61300311121" WURTH_61300311121 5830,3550 r0 top
J5_1 "971" Keystone_971 4650,5850 r0 top (schematic designator J5)
J5_2 "971" Keystone_971 4650,8370 r0 top (schematic designator J5)
J6_1 "61300311121" WURTH_61300311121 5850,4470 r0 top (schematic designator J6)
J6_2 "61300311121" WURTH_61300311121 5850,6990 r0 top (schematic designator J6)
J7_1 "61300311121" WURTH_61300311121 5850,5390 r0 top (schematic designator J7)
J7_2 "61300311121" WURTH_61300311121 5850,7910 r0 top (schematic designator J7)
J8_1 "972" Keystone_972 4650,5050 r0 top (schematic designator J8)
J8_2 "972" Keystone_972 4650,7570 r0 top (schematic designator J8)
J9_1 "TESTPOINT_2Pos" "HIRSCHMANN_973 582-101" 11850,4030 r0 top (schematic designator J9)
J9_2 "TESTPOINT_2Pos" "HIRSCHMANN_973 582-101" 11850,6550 r0 top (schematic designator J9)
J10_1 "Suggest using a net name here" Harwin_H3492-01 10900,4750 r180 top (schematic designator J10)
J10_2 "Suggest using a net name here" Harwin_H3492-01 10900,7270 r180 top (schematic designator J10)
J11_1 "Suggest using a net name here" Harwin_H3492-01 11220,4750 r180 top (schematic designator J11)
J11_2 "Suggest using a net name here" Harwin_H3492-01 11220,7270 r180 top (schematic designator J11)
J12_1 "TESTPOINT_2Pos" "HIRSCHMANN_973 582-100" 11850,4590 r0 top (schematic designator J12)
J12_2 "TESTPOINT_2Pos" "HIRSCHMANN_973 582-100" 11850,7110 r0 top (schematic designator J12)
J13_1 "TESTPOINT_2Pos" "HIRSCHMANN_973 582-101" 11850,5270 r0 top (schematic designator J13)
J13_2 "TESTPOINT_2Pos" "HIRSCHMANN_973 582-101" 11850,7790 r0 top (schematic designator J13)
J14_1 "Suggest using a net name here" Harwin_H3492-01 10900,5110 r180 top (schematic designator J14)
J14_2 "Suggest using a net name here" Harwin_H3492-01 10900,7630 r180 top (schematic designator J14)
J15_1 "Suggest using a net name here" Harwin_H3492-01 11220,5110 r0 top (schematic designator J15)
J15_2 "Suggest using a net name here" Harwin_H3492-01 11220,7630 r0 top (schematic designator J15)
J16_1 "TESTPOINT_2Pos" "HIRSCHMANN_973 582-100" 11850,5830 r0 top (schematic designator J16)
J16_2 "TESTPOINT_2Pos" "HIRSCHMANN_973 582-100" 11850,8350 r0 top (schematic designator J16)
J17_1 "61300311121" WURTH_61300311121 6205,4795 r180 top (schematic designator J17)
J17_2 "61300311121" WURTH_61300311121 6205,7315 r180 top (schematic designator J17)
J18_1 "61300311121" WURTH_61300311121 5580,3000 r0 top (schematic designator J18)
J18_2 "61300311121" WURTH_61300311121 6510,3000 r0 top (schematic designator J18)
J19 "TESTPOINT_2Pos" "HIRSCHMANN_973 582-101" 11850,2185 r0 top
J20 "TESTPOINT_2Pos" "HIRSCHMANN_973 582-100" 11850,2535 r0 top
L1 "LPS6235-334MLB" LPS6235 5750,1450 r0 top
L2 "XPL2010-501MLB" XPL2010 6010,1460 r90 top
L3 "LPS4012-105MLB" LPS4012 6450,1430 r0 top
L4 "XPL2010-501MLB" XPL2010 6690,1460 r90 top
L5_1 "SER2918H-103KL" SER2918H 8380,4430 r90 top (schematic designator L5)
L5_2 "SER2918H-103KL" SER2918H 8380,6950 r90 top (schematic designator L5)
L6_1 "SER2918H-103KL" SER2918H 10060,4190 r270 top (schematic designator L6)
L6_2 "SER2918H-103KL" SER2918H 10060,6710 r270 top (schematic designator L6)
L7_1 "SER2918H-103KL" SER2918H 10060,5670 r90 top (schematic designator L7)
L7_2 "SER2918H-103KL" SER2918H 10060,8190 r90 top (schematic designator L7)
L8_1 "SER2918H-103KL" SER2918H 8380,5430 r270 top (schematic designator L8)
L8_2 "SER2918H-103KL" SER2918H 8380,7950 r270 top (schematic designator L8)
L9 "SER2918H-103KL" SER2918H 9290,2900 r180 top
L10 "100nH" IHLP-2525AH 8990,2180 r270 top
L11 "SER2918H-103KL" SER2918H 9290,1460 r180 top
Q1 "2N7002E" SOT-23 4840,2320 r90 top
Q2 "2N7002E" SOT-23 4840,1540 r90 top
Q3 "SQD50N06-09L" DPAK 10230,3260 r180 bottom
Q4 "SQD50N06-09L" DPAK 10230,2820 r180 bottom
Q5 "SQD50N06-09L" DPAK 10170,2380 r0 bottom
Q6 "CSD17570Q5B" TRANS_NexFET_Q5B 11760,2530 r270 bottom
Q7 "SQD50N06-09L" DPAK 10230,1380 r180 bottom
Q8 "SQD50N06-09L" DPAK 10230,1820 r180 bottom
Q9 "SQD50N06-09L" DPAK 10170,940 r0 bottom
Q10 "CSD17570Q5B" TRANS_NexFET_Q5B 11995,2530 r270 bottom
R1 "CRCW060347K5FKEA" 0603 4950,2320 r90 top
R2 "CRCW06033K32FKEA" 0603 4840,2440 r0 top
R3 "CRCW060310K0FKEA" 0603 4970,2920 r0 top
R4 "CRCW0603100RFKEA" 0603 4840,2200 r180 top
R5 "CRCW060380K6FKEA" 0603 5090,3100 r270 top
R6 "CRCW060310K0FKEA" 0603 4970,3200 r0 top
R7 "CRCW060347K5FKEA" 0603 4840,1420 r0 top
R8 "CRCW06033K32FKEA" 0603 4840,1660 r0 top
R9 "CRCW060349R9FKEA" 0603 6030,910 r90 top
R10 "CRCW06031K00FKEA" 0603 5790,910 r90 top
R11 "CRCW060314K7FKEA" 0603 5870,910 r270 top
R12 "CRCW060311K0FKEA" 0603 5340,1380 r270 top
R13 "CRCW06032K94FKEA" 0603 5230,1380 r270 top
R14 "CRCW06032K94FKEA" 0603 5120,1380 r270 top
R15 "CRCW0603200RFKEA" 0603 5010,1380 r270 top
R16 "CRCW06031K00FKEA" 0603 6670,940 r0 top
R17 "CRCW060349R9FKEA" 0603 6670,860 r180 top
R18 "CRCW060314K7FKEA" 0603 6470,900 r270 top
R19_1 "CRCW0603100RFKEA" 0603 6120,4950 r0 top (schematic designator R19)
R19_2 "CRCW0603100RFKEA" 0603 6120,7470 r0 top (schematic designator R19)
R20_1 "CRCW0603100RFKEA" 0603 4680,4540 r270 bottom (schematic designator R20)
R20_2 "CRCW0603100RFKEA" 0603 4680,7060 r270 bottom (schematic designator R20)
R21_1 "CRCW040210K0FKED" 0402 5850,4750 r0 bottom (schematic designator R21)
R21_2 "CRCW040210K0FKED" 0402 5850,7270 r0 bottom (schematic designator R21)
R22_1 "CRCW060313K7FKEA" 0603 5400,5620 r270 top (schematic designator R22)
R22_2 "CRCW060313K7FKEA" 0603 5400,8140 r270 top (schematic designator R22)
R23_1 "CRCW06030000Z0EA" 0603 4810,5640 r0 bottom (schematic designator R23)
R23_2 "CRCW06030000Z0EA" 0603 4810,8160 r0 bottom (schematic designator R23)
R24_1 "CRCW0603100KFKEA" 0603 5180,4300 r270 bottom (schematic designator R24)
R24_2 "CRCW0603100KFKEA" 0603 5180,6820 r270 bottom (schematic designator R24)
R25_1 "CRCW060310K0FKEA" 0603 5370,5190 r180 top (schematic designator R25)
R25_2 "CRCW060310K0FKEA" 0603 5370,7710 r180 top (schematic designator R25)
R26_1 "CRCW0603100RFKEA" 0603 6120,5030 r0 top (schematic designator R26)
R26_2 "CRCW0603100RFKEA" 0603 6120,7550 r0 top (schematic designator R26)
R27_1 "CRCW040210K0FKED" 0402 5850,4630 r180 bottom (schematic designator R27)
R27_2 "CRCW040210K0FKED" 0402 5850,7150 r180 bottom (schematic designator R27)
R28_1 "CRCW060320K0FKEA" 0603 5530,5090 r180 top (schematic designator R28)
R28_2 "CRCW060320K0FKEA" 0603 5530,7610 r180 top (schematic designator R28)
R29_1 "PTD902-2015F-A103" Bourns_PTD902 4490,4270 r270 top (schematic designator R29)
R29_2 "PTD902-2015F-A103" Bourns_PTD902 4490,6790 r270 top (schematic designator R29)
R30_1 "CRCW060310K0FKEA" 0603 5400,4100 r180 top (schematic designator R30)
R30_2 "CRCW060310K0FKEA" 0603 5400,6620 r180 top (schematic designator R30)
R31_1 "CRCW060324K3FKEA" 0603 5400,4180 r180 top (schematic designator R31)
R31_2 "CRCW060324K3FKEA" 0603 5400,6700 r180 top (schematic designator R31)
R32_1 "CRCW06030000Z0EA" 0603 4610,4340 r90 bottom (schematic designator R32)
R32_2 "CRCW06030000Z0EA" 0603 4610,6860 r90 bottom (schematic designator R32)
R33_1 "CRCW060320K0FKEA" 0603 5530,5190 r180 top (schematic designator R33)
R33_2 "CRCW060320K0FKEA" 0603 5530,7710 r180 top (schematic designator R33)
R34_1 "CRCW06034K53FKEA" 0603 5500,5620 r270 top (schematic designator R34)
R34_2 "CRCW06034K53FKEA" 0603 5500,8140 r270 top (schematic designator R34)
R35_1 "CRCW06036K81FKEA" 0603 5370,5090 r0 top (schematic designator R35)
R35_2 "CRCW06036K81FKEA" 0603 5370,7610 r0 top (schematic designator R35)
R36_1 "CRCW0603100RFKEA" 0603 6120,5230 r0 top (schematic designator R36)
R36_2 "CRCW0603100RFKEA" 0603 6120,7750 r0 top (schematic designator R36)
R37_1 "CRCW0603100RFKEA" 0603 4790,4540 r270 bottom (schematic designator R37)
R37_2 "CRCW0603100RFKEA" 0603 4790,7060 r270 bottom (schematic designator R37)
R38_1 "CRCW040210K0FKED" 0402 5850,5110 r0 bottom (schematic designator R38)
R38_2 "CRCW040210K0FKED" 0402 5850,7630 r0 bottom (schematic designator R38)
R39_1 "CRCW040210K0FKED" 0402 5850,5230 r180 bottom (schematic designator R39)
R39_2 "CRCW040210K0FKED" 0402 5850,7750 r180 bottom (schematic designator R39)
R40_1 "CRCW06030000Z0EA" 0603 4810,4840 r0 bottom (schematic designator R40)
R40_2 "CRCW06030000Z0EA" 0603 4810,7360 r0 bottom (schematic designator R40)
R41_1 "CRCW0603100KFKEA" 0603 5180,4440 r90 bottom (schematic designator R41)
R41_2 "CRCW0603100KFKEA" 0603 5180,6960 r90 bottom (schematic designator R41)
R42_1 "CRCW0603100RFKEA" 0603 6120,5150 r0 top (schematic designator R42)
R42_2 "CRCW0603100RFKEA" 0603 6120,7670 r0 top (schematic designator R42)
R43_1 "CRCW060310K0FKEA" 0603 5450,4640 r180 top (schematic designator R43)
R43_2 "CRCW060310K0FKEA" 0603 5450,7160 r180 top (schematic designator R43)
R44_1 "CRCW060324K3FKEA" 0603 5450,4560 r180 top (schematic designator R44)
R44_2 "CRCW060324K3FKEA" 0603 5450,7080 r180 top (schematic designator R44)
R45_1 "CRCW06033R32FKEA" 0603 9300,3970 r90 bottom (schematic designator R45)
R45_2 "CRCW06033R32FKEA" 0603 9300,6490 r90 bottom (schematic designator R45)
R46_1 "CRCW06033R32FKEA" 0603 6470,4570 r180 bottom (schematic designator R46)
R46_2 "CRCW06033R32FKEA" 0603 6470,7090 r180 bottom (schematic designator R46)
R47_1 "CRCW06033R32FKEA" 0603 10820,4370 r270 bottom (schematic designator R47)
R47_2 "CRCW06033R32FKEA" 0603 10820,6890 r270 bottom (schematic designator R47)
R48_1 "CRCW06033R32FKEA" 0603 6475,4570 r180 top (schematic designator R48)
R48_2 "CRCW06033R32FKEA" 0603 6475,7090 r180 top (schematic designator R48)
R49_1 "CRCW060322K1FKEA" 0603 6470,4765 r0 bottom (schematic designator R49)
R49_2 "CRCW060322K1FKEA" 0603 6470,7285 r0 bottom (schematic designator R49)
R50_1 "CRCW06033R32FKEA" 0603 10820,5490 r90 bottom (schematic designator R50)
R50_2 "CRCW06033R32FKEA" 0603 10820,8010 r90 bottom (schematic designator R50)
R51_1 "CRCW06033R32FKEA" 0603 6470,5295 r180 bottom (schematic designator R51)
R51_2 "CRCW06033R32FKEA" 0603 6470,7815 r180 bottom (schematic designator R51)
R52_1 "CRCW06033R32FKEA" 0603 9300,5890 r270 bottom (schematic designator R52)
R52_2 "CRCW06033R32FKEA" 0603 9300,8410 r270 bottom (schematic designator R52)
R53_1 "CRCW060310K0FKEA" 0603 6470,4830 r0 bottom (schematic designator R53)
R53_2 "CRCW060310K0FKEA" 0603 6470,7350 r0 bottom (schematic designator R53)
R54_1 "CRCW06030000Z0EA" 0603 6470,4895 r0 bottom (schematic designator R54)
R54_2 "CRCW06030000Z0EA" 0603 6470,7415 r0 bottom (schematic designator R54)
R55_1 "CRCW060310K0FKEA" 0603 5920,2710 r90 top (schematic designator R55)
R55_2 "CRCW060310K0FKEA" 0603 6850,2710 r90 top (schematic designator R55)
R56_1 "CRCW060310K0FKEA" 0603 5380,2180 r90 top (schematic designator R56)
R56_2 "CRCW060310K0FKEA" 0603 6310,2180 r90 top (schematic designator R56)
R57_1 "CRCW060323K7FKEA" 0603 5860,2070 r90 top (schematic designator R57)
R57_2 "CRCW060323K7FKEA" 0603 6790,2070 r90 top (schematic designator R57)
R58_1 "CRCW06031K00FKEA" 0603 5780,2220 r90 top (schematic designator R58)
R58_2 "CRCW06031K00FKEA" 0603 6710,2220 r90 top (schematic designator R58)
R59_1 "CRCW060310K0FKEA" 0603 5800,2710 r270 top (schematic designator R59)
R59_2 "CRCW060310K0FKEA" 0603 6730,2710 r270 top (schematic designator R59)
R60_1 "CRCW0603200KFKEA" 0603 5380,1960 r90 top (schematic designator R60)
R60_2 "CRCW0603200KFKEA" 0603 6310,1960 r90 top (schematic designator R60)
R61_1 "CRCW060310K0FKEA" 0603 5780,1920 r270 top (schematic designator R61)
R61_2 "CRCW060310K0FKEA" 0603 6710,1920 r270 top (schematic designator R61)
R62_1 "CRCW0603365KFKEA" 0603 5780,2070 r90 top (schematic designator R62)
R62_2 "CRCW0603365KFKEA" 0603 6710,2070 r90 top (schematic designator R62)
R63_1 "CRCW060310K0FKEA" 0603 5240,2710 r270 top (schematic designator R63)
R63_2 "CRCW060310K0FKEA" 0603 6170,2710 r270 top (schematic designator R63)
R64_1 "CRCW060310K0FKEA" 0603 5360,2710 r270 top (schematic designator R64)
R64_2 "CRCW060310K0FKEA" 0603 6290,2710 r270 top (schematic designator R64)
R65_1 "CRCW060310K0FKEA" 0603 5580,2740 r180 top (schematic designator R65)
R65_2 "CRCW060310K0FKEA" 0603 6510,2740 r180 top (schematic designator R65)
R66_1 "CRCW060310K0FKEA" 0603 5580,2820 r180 top (schematic designator R66)
R66_2 "CRCW060310K0FKEA" 0603 6510,2820 r180 top (schematic designator R66)
R67 "CRCW06030000Z0EA" 0603 7960,2730 r90 top
R68 "CRCW060330K1FKEA" 0603 8350,3440 r180 top
R69 "CRCW06033R32FKEA" 0603 8350,3510 r180 top
R70 "CRCW06030000Z0EA" 0603 8100,980 r90 top
R71 "CRCW06033R32FKEA" 0603 8300,1620 r90 top
R72 "CRCW06030000Z0EA" 0603 8580,3040 r270 top
R73 "CRCW06030000Z0EA" 0603 8580,1290 r270 top
R74 "CRCW0603100KFKEA" 0603 8200,3110 r90 top
R75 "CRCW06030000Z0EA" 0603 8720,2730 r90 top
R76 "CRCW06030000Z0EA" 0603 8720,980 r90 top
R77 "CRCW060349R9FKEA" 0603 8040,2970 r90 top
R78 "CRCW0603100KFKEA" 0603 8040,3110 r270 top
R79 "CRCW06030000Z0EA" 0603 8030,2730 r270 top
R80 "CRCW06037K68FKEA" 0603 8350,3370 r0 top
R81 "CRCW060320K0FKEA" 0603 7890,2730 r90 top
R82 "CRCW060337K4FKEA" 0603 8160,3220 r0 top
R83 "CRCW06030000Z0EA" 0603 8100,2730 r90 top
R84 "CRCW060320K0FKEA" 0603 8030,980 r90 top
R85 "CRCW06033K74FKEA" 0603 8120,3110 r270 top
R86 "CRCW060344K2FKEA" 0603 8040,3260 r270 top
R87 "CRCW20108R20JNEF" 2010 10130,2600 r0 bottom
R88 "ERJ-M1WTF1M5U" 2512 10190,3360 r180 top
R89 "CRCW06031K00FKEA" 0603 11908.5,2865 r180 bottom
R90 "CRCW20108R20JNEF" 2010 10270,3040 r180 bottom
R91 "CRCW06031K00FKEA" 0603 8690,3280 r0 top
R92 "CRCW06031K00FKEA" 0603 8690,3200 r0 top
R93 "CRCW06034R75FKEA" 0603 8390,2730 r270 top
R94 "CRCW06034R75FKEA" 0603 8170,2730 r270 top
R95 "CRCW06034R75FKEA" 0603 8690,2920 r0 top
R96 "ERJ-1TRQJR68U" 2512 9260,2180 r270 top
R97 "CRCW20108R20JNEF" 2010 10130,1160 r0 bottom
R98 "ERJ-M1WTF1M5U" 2512 10190,1920 r180 top
R99 "CRCW20108R20JNEF" 2010 10270,1600 r180 bottom
R100 "CRCW06031K00FKEA" 0603 8690,1530 r0 top
R101 "CRCW06031K00FKEA" 0603 8690,1450 r0 top
R102 "CRCW06034R75FKEA" 0603 8170,980 r270 top
R103 "CRCW06034R75FKEA" 0603 8390,980 r270 top
R104 "CRCW06034R75FKEA" 0603 8690,1170 r0 top
S1 "431256038716" SW_1825027-2 4660,3100 r270 top
U1 "TPS3803-01-Q1" DCK0005A_N 4970,3100 r0 top
U2 "LM2841X-Q1" MK06A_N 5830,1090 r90 top
U3 "LM2841X-Q1" MK06A_N 6510,1090 r90 top
U4 "TPS7A6633-Q1" DGN0008D_N 5080,950 r90 top
U5_1 "OPA1662A-Q1" D0008A_N 5450,4370 r90 top (schematic designator U5)
U5_2 "OPA1662A-Q1" D0008A_N 5450,6890 r90 top (schematic designator U5)
U6_1 "OPA1662AIDGKRQ1" DGK0008A_N 5850,4930 r90 bottom (schematic designator U6)
U6_2 "OPA1662AIDGKRQ1" DGK0008A_N 5850,7450 r90 bottom (schematic designator U6)
U7_1 "OPA1662A-Q1" D0008A_N 5450,5390 r90 top (schematic designator U7)
U7_2 "OPA1662A-Q1" D0008A_N 5450,7910 r90 top (schematic designator U7)
U8_1 "TPA3251D2" DDV0044D_N 6830,4930 r0 bottom (schematic designator U8)
U8_2 "TPA3251D2" DDV0044D_N 6830,7450 r0 bottom (schematic designator U8)
U9_1 "LM2904-Q1" D0008A_N 5580,2070 r0 top (schematic designator U9)
U9_2 "LM2904-Q1" D0008A_N 6510,2070 r0 top (schematic designator U9)
U10_1 "LM2904-Q1" D0008A_N 5580,2510 r180 top (schematic designator U10)
U10_2 "LM2904-Q1" D0008A_N 6510,2510 r180 top (schematic designator U10)
U11 "LM25122-Q1" PWP0020A_N 8390,3030 r270 top
U12 "LM25122-Q1" PWP0020A_N 8390,1290 r270 top

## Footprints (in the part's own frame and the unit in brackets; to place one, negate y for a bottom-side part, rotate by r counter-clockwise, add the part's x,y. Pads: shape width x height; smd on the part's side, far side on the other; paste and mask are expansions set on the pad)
0402 [mm] "0402 from SM-752 data"
  rect 0.8x0.6 smd: 1(-0.6,0) 2(0.6,0)
  silkscreen extent -1.22,-0.52 1.22,0.52, body extent -0.55,-0.3 0.55,0.3, height 0.6
551-0403_Red [mm] "TH, 2-Leads, Body 4.57x4.57mm, Pitch 2.55mm"
  rect 1.65x1.65 hole 1.143: 1(-1.275,1.275)
  round 1.65 hole 1.143: 2(-1.275,-1.275)
  round 1.24 hole 1.24 unplated mask+0: MH1(1.275,1.275) MH2(1.275,-1.275)
  silkscreen extent -2.8,-2.38 2.39,2.39, body extent -2.38,-2.38 6.34,2.39, height 9.02
0603 [mm] "0603 from SM-752 data"
  rect 1x0.95 smd: 1(-0.8,0) 2(0.8,0)
  silkscreen extent -1.52,-0.69 1.52,0.69, body extent -0.87,-0.47 0.87,0.47, height 1
0805_HV [mil] "0805 with 30mil clearance between pads"
  rect 50x63 smd: 1(-40,0) 2(40,0)
  silkscreen extent -74,-40 74,40, body extent -43,-29 43,29, height 57
1206 [mm] "1206 from SM-752 data"
  rect 1.3x1.85 smd: 1(-1.45,0) 2(1.45,0)
  silkscreen extent -2.4,-1.21 2.4,1.21, body extent -1.7,-0.9 1.7,0.9, height 1.35
1210 [mm] "1210 from SM-752 data"
  rect 1.3x2.7 smd: 1(-1.45,0) 2(1.45,0)
  silkscreen extent -2.32,-1.57 2.32,1.57, body extent -1.7,-1.35 1.7,1.35, height 1.35
2010 [mm] "Chip Capacitor, Body 5.08x2.54mm, IPC Medium Density"
  rect 1.6x2.7 smd: 1(-2.3,0) 2(2.3,0)
  silkscreen extent -3.42,-1.65 3.42,1.65, body extent -2.73,-1.45 2.73,1.45, height 1.66
2512 [mm] "Chip Resistor, Body 6.3x3.2mm, IPC Medium Density"
  rect 1.3x3.4 smd: 1(-2.95,0) 2(2.95,0)
  silkscreen extent -1.9,-1.6 1.9,1.6, body extent -3.22,-1.67 3.22,1.67, height 0.71
Bourns_PTD902 [mm] "TH, 6-Leads, Body 9.5x9.65mm, Pitch 2.5mm"
  rect 1.5x1.5 hole 1: 1(-2.5,5)
  round 1.5 hole 1: 1'(-2.5,7.5) 2(0,5) 2'(0,7.5) 3(2.5,5) 3'(2.5,7.5)
  silkscreen extent -5.25,0.15 4.75,9.65, body extent -4.75,-15 4.75,9.65, height 11.3
D0008A_N [mm] "SOIC, 8-Leads, Body 4.9x3.9mm, Pitch 1.27mm, IPC Medium Density"
  oval 1.45x0.6 smd: 1(-2.725,1.905) 2(-2.725,0.635) 3(-2.725,-0.635) 4(-2.725,-1.905) 5(2.725,-1.905) 6(2.725,-0.635) 7(2.725,0.635) 8(2.725,1.905)
  silkscreen extent -3.3,-2.5 0.9,2.5, body extent -3,-2.45 3,2.45, height 1.63
DCK0005A_N [mm] "SOT353, 5-Leads, Body 2x1.3mm, Pitch 0.65mm, Lead Span 2.1mm, IPC Medium Density"
  rrect25% 0.85x0.4 smd: 1(-1.125,0.65) 2(-1.125,0) 3(-1.125,-0.65) 4(1.125,-0.65) 5(1.125,0.65)
  silkscreen extent -1.48,-1.02 0.55,1.1, body extent -1.14,-1 1.14,1, height 0.95
DDV0044D_N [mm] "SOP, 44-Leads, Body 14.1x6.2mm, Pitch 0.635mm, IPC Medium Density"
  oval 1.4x0.4 smd: 1(-3.8,6.667) 2(-3.8,6.032) 3(-3.8,5.397) 4(-3.8,4.763) 5(-3.8,4.127) 6(-3.8,3.492) 7(-3.8,2.857) 8(-3.8,2.222) 9(-3.8,1.587) 10(-3.8,0.953) 11(-3.8,0.318) 12(-3.8,-0.318) 13(-3.8,-0.953) 14(-3.8,-1.587) 15(-3.8,-2.222) 16(-3.8,-2.857) 17(-3.8,-3.492) 18(-3.8,-4.127) 19(-3.8,-4.763) 20(-3.8,-5.397) 21(-3.8,-6.032) 22(-3.8,-6.667) 23(3.8,-6.667) 24(3.8,-6.032) 25(3.8,-5.397) 26(3.8,-4.763) 27(3.8,-4.127) 28(3.8,-3.492) 29(3.8,-2.857) 30(3.8,-2.222) 31(3.8,-1.587) 32(3.8,-0.953) 33(3.8,-0.318) 34(3.8,0.318) 35(3.8,0.953) 36(3.8,1.587) 37(3.8,2.222) 38(3.8,2.857) 39(3.8,3.492) 40(3.8,4.127) 41(3.8,4.763) 42(3.8,5.397) 43(3.8,6.032) 44(3.8,6.667)
  silkscreen extent -4.35,-7.05 2.7,7.12, body extent -4.06,-7 4.06,7, height 1.2
DGK0008A_N [mm] "TSOP, 8-Leads, Body 3x3mm, Pitch 0.65mm, IPC Medium Density"
  oval 1.35x0.45 smd: 1(-2.225,0.975) 2(-2.225,0.325) 3(-2.225,-0.325) 4(-2.225,-0.975) 5(2.225,-0.975) 6(2.225,-0.325) 7(2.225,0.325) 8(2.225,0.975)
  silkscreen extent -2.75,-1.55 0.95,1.55, body extent -2.45,-1.5 2.45,1.5, height 0.96
DGN0008D_N [mm] "TSOP, 8-Leads, Body 3x3mm, Pitch 0.65mm, Thermal Pad 1.89x1.57mm, IPC Medium Density"
  rrect100% 1.35x0.45 smd: 1(-2.225,0.975) 2(-2.225,0.325) 3(-2.225,-0.325) 4(-2.225,-0.975) 5(2.225,-0.975) 6(2.225,-0.325) 7(2.225,0.325) 8(2.225,0.975)
  rrect6% 1.57x1.89 smd: 9(0,0)
  silkscreen extent -2.73,-1.55 0.95,1.55, body extent -2.46,-1.5 2.46,1.5, height 1.1
DPAK [mm] "D-PAK, 3-Pads, Body 6.22x6.73mm (max), TO-252AA using nominal STEP model"
  rrect6% 2.6x1.6 smd: 1(-3.4,2.28) 3(-3.4,-2.28)
  rrect2% 6.2x5.8 smd paste-2.9: 4(3.4,0)
  silkscreen extent -4.5,-3.3 4.7,3.28, body extent -3.86,-3.29 5.84,3.29, height 2.48
Fiducial10-30 [mm]
  round 1 smd mask+1: 1(0,0)
  Top keep-out circle w1.678: c0,0 r0.75
Harwin_H3492-01 [mm] "Pin Receptacle, Dia 4 mm, TH"
  round 5.12 hole 4.12: 1(0,0)
  silkscreen extent -2.9,-2.9 2.9,2.9, body extent -2.35,-2.36 2.37,2.36, height 0.8
"HIRSCHMANN_973 582-100" [mil] "Hirschmann Automation and Control GmbH"
  rect 85x85 hole 55: 1(-364.17,0)
  round 85 hole 55: 2(364.17,0)
  body extent -414,-157 413,157, height 413
"HIRSCHMANN_973 582-101" [mil] "Hirschmann Automation and Control GmbH"
  rect 85x85 hole 55: 1(-364.17,0)
  round 85 hole 55: 2(364.17,0)
  body extent -414,-157 413,157, height 413
IHLP-2525AH [mm] "Vishay Dale"
  rect 1.83x3.43 smd: 1(-2.77,0) 2(2.77,0)
  silkscreen extent -3.7,-3.4 3.7,3.4, body extent -3.62,-3.36 3.62,3.36, height 1.8
Keystone_971 [mm] "PC Mount Phono Jack-Red, TH"
  round 2.6 hole 2.08: 1(0,0) 3(9.8,0)
  round 3.4 hole 2.87: 4(8,-5.3)
  round 0 hole 1.98 unplated: M1(0,3.745) M2(0,-3.745)
  round 0 hole 2.08 unplated: M3(6.5,0)
  silkscreen extent -3.99,-5.01 10.03,5.01, body extent -13.31,-5.44 10.05,5, height 13.02
Keystone_972 [mm] "RCA Jack, Black, R/A, TH"
  round 2.6 hole 2.08: 1(0,0) 3(9.8,0)
  round 3.4 hole 2.87: 4(8,-5.3)
  round 0 hole 1.98 unplated: M1(0,3.745) M2(0,-3.745)
  round 0 hole 2.08 unplated: M3(6.5,0)
  silkscreen extent -3.99,-5.01 10.03,5.01, body extent -13.32,-5.41 10.03,5.03, height 12.51
LPS4012 [mm] "Coilcraft recommended land pattern.  Document 433-2, rev 10/20/08"
  rect 0.7x3.124 smd: 1(-1.881,0) 2(1.881,0)
  rect 0.902x0.801 smd rot 135: 1(-1.592,-1.605) 2(1.592,1.605)
  rect 0.902x0.801 smd rot 45: 1(-1.592,1.605) 2(1.592,-1.605)
  rect 0.812x0.7 smd: 1(-1.168,-1.85) 1(-1.168,1.85) 2(1.168,-1.85) 2(1.168,1.85)
  silkscreen extent -3.26,-2.6 2.55,2.6, body extent -2.05,-2.05 2.05,2.05, height 1.22
LPS6235 [mm] "Coilcraft recommended land pattern.  Document 587-2, rev 10/17/08"
  rect 1.2x4.25 smd: 1(-2.7,0) 2(2.7,0)
  rect 1.68x1.6 smd rot 135: 1(-2.126,-2.151) 2(2.126,2.151)
  rect 1.68x1.6 smd rot 45: 1(-2.126,2.151) 2(2.126,-2.151)
  rect 1.125x1.2 smd: 1(-1.562,-2.7) 1(-1.562,2.7) 2(1.562,-2.7) 2(1.562,2.7)
  silkscreen extent -3.7,-3.7 3.7,3.7, body extent -3.1,-3.1 3.1,3.1, height 3.52
MK06A_N [mm] "SOT23, 6-Leads, Body 3.0x1.7mm, Pitch 0.95mm, Lead Span 2.9mm, IPC Medium Density"
  rect 1.1x0.65 smd: 1(-1.2,0.95) 2(-1.2,0) 3(-1.2,-0.95) 4(1.2,-0.95) 5(1.2,0) 6(1.2,0.95)
  silkscreen extent -1.32,-1.55 0.25,1.95, body extent -0.9,-1.55 0.9,1.55, height 1
PHE426_1800x950x1750 [mm] "TH, 2-Leads, 18x9.5mm, Pin Spacing 15mm"
  round 1.55 hole 1.05: 1(-7.5,0) 2(7.5,0)
  silkscreen extent -9,-4.75 9,4.75, body extent -9,-4.75 9,4.75, height 17.5
PW_1800x2000 [mm] "TH, 2-Leads, Dia 18mm, Pin Spacing 7.5mm"
  rect 1.55x1.55 hole 1.05: 1(-3.75,0)
  round 1.55 hole 1.05: 2(3.75,0)
  silkscreen extent -9.25,-9.25 9.25,9.25, body extent -9.18,-9.23 9.22,9.24, height 22.01
PWP0020A_N [mm] "TSOP, 20-Leads, Body 6.5x4.4mm, Pitch 0.65mm, Exposed Pad, IPC Medium Density"
  rrect100% 1.4x0.45 smd: 1(-2.95,2.925) 2(-2.95,2.275) 3(-2.95,1.625) 4(-2.95,0.975) 5(-2.95,0.325) 6(-2.95,-0.325) 7(-2.95,-0.975) 8(-2.95,-1.625) 9(-2.95,-2.275) 10(-2.95,-2.925) 11(2.95,-2.925) 12(2.95,-2.275) 13(2.95,-1.625) 14(2.95,-0.975) 15(2.95,-0.325) 16(2.95,0.325) 17(2.95,0.975) 18(2.95,1.625) 19(2.95,2.275) 20(2.95,2.925)
  rrect3% 3x4.2 smd: 21(0,0)
  silkscreen extent -3.55,-3.3 1.5,3.4, body extent -3.21,-3.25 3.21,3.25, height 1
R82_720x250x650 [mm] "TH, 2-Leads, Body 7.2x2.5mm, Lead Spacing 5mm"
  round 1.3 hole 0.8: 1(-2.5,0) 2(2.5,0)
  silkscreen extent -3.7,-1.3 3.7,1.3, body extent -3.7,-1.3 3.7,1.3, height 6.6
R82_720x720x1300 [mm] "TH, 2-Leads, Body 7.2x7.2mm, Lead Spacing 5mm"
  round 1.4 hole 0.9: 1(-2.5,0) 2(2.5,0)
  silkscreen extent -3.75,-3.65 3.75,3.65, body extent -3.75,-3.65 3.75,3.65, height 13.1
SER2918H [mm] "COILCRAFT"
  rect 5.59x5.33 smd: 1(-14.355,5.075) 2(-14.455,-5.075)
  rect 6.35x5.28 smd: 3(8.25,0)
  silkscreen extent -11.04,-14 10.81,13.9, body extent -16.7,-14.05 11.22,13.85, height 17.82
SMC [mil] "Molded Diode, 2-Leads, Body 6.9x5.8mm, IPC Medium Density, based on OnSemi component dimensions and land patterns"
  rect 110x150 smd: 1(-140.49,0) 2(140.49,0)
  silkscreen extent -221,-124 189,123, body extent -156,-116 156,116, height 91
SOD-123F [mm] "NXP recommended land pattern"
  rect 1.2x1.2 smd paste-0.05: 1(-1.4,0) 2(1.4,0)
  silkscreen extent -2.64,-1.12 2.01,1.12, body extent -1.8,-0.85 1.8,0.85, height 1.2
SOD-123FL [mm] "Copied from SOD-123"
  rect 0.915x1.22 smd: 1(-1.637,0) 2(1.637,0)
  silkscreen extent -2.74,-1.16 1.68,1.16, body extent -1.9,-0.9 1.9,0.9, height 1
sod-323 [mm] "NXP recommended land pattern"
  rect 0.6x0.6 smd paste-0.05: 1(-1.1,0) 2(1.1,0)
  silkscreen extent -2.06,-0.86 1.53,0.86, body extent -1.3,-0.67 1.3,0.68, height 1.1
SOT-23 [mm] "SOT23, 3-Leads, Body 2.9x1.3mm, Pitch 0.95mm, Lead Span 2.5mm, IPC Medium Density"
  rrect50% 1x0.6 smd: 1(-1.2,0.95) 2(-1.2,-0.95) 3(1.2,0)
  silkscreen extent -1.63,-1.5 0.7,1.5, body extent -1.16,-1.45 1.21,1.45, height 1
SW_1825027-2 [mm] "TH, 2-Leads, Body 7.11x7.16mm"
  round 1.5 hole 0.99: 1(-2.25,-1.245) 2(2.25,-1.245)
  round 1.8 hole 1.3: MH1(-3.505,1.245) MH2(3.505,1.245)
  silkscreen extent -3.56,-3.83 3.56,-0.14, body extent -4.2,-4.38 4.2,2.77, height 7.01
TRANS_NexFET_Q5B [mm] "TI recommended land pattern (nominal) November 2012"
  rect 1.372x0.71 smd paste-0.4: 1(-2.776,1.905) 2(-2.776,0.635) 3(-2.776,-0.635) 4(-2.776,-1.905)
  rect 0.59x0.71 smd paste-0.3: 5(2.776,-1.905) 6(2.776,-0.635) 7(2.776,0.635) 8(2.776,1.905)
  Top region: -1.106,2.26 2.744,2.26 2.744,-2.26 -1.106,-2.26
  silkscreen extent -3.38,-2.7 3,2.7, body extent -3.23,-2.55 2.87,2.55, height 1.06
WL-SMCW_GREEN [mm] "WURTH"
  rect 0.8x0.8 smd: 1(-0.8,0) 2(0.8,0)
  silkscreen extent -1.9,-0.8 1.2,0.8, body extent -0.85,-0.45 0.85,0.45, height 0.8
WURTH_61300211121 [mm] "Header, 2.54mm, 2x1, TH"
  rect 1.65x1.65 hole 1.15: 1(-1.27,0)
  round 1.65 hole 1.15: 2(1.27,0)
  silkscreen extent -2.54,-1.27 2.54,1.6, body extent -2.54,-1.27 2.54,1.27, height 8.54
WURTH_61300311121 [mm] "Header, 2.54mm, 3x1, TH"
  rect 1.65x1.65 hole 1.15: 1(-2.54,0)
  round 1.65 hole 1.15: 2(0,0) 3(2.54,0)
  silkscreen extent -3.81,-1.27 3.81,1.6, body extent -3.81,-1.27 3.81,1.27, height 8.54
XPL2010 [mm] "Coilcraft recommended land pattern Document 646-2 Revised 3/28/11"
  rect 1.04x2.2 smd: 1(-0.725,0) 2(0.725,0)
  silkscreen extent -1.52,-1.4 1.52,1.4, body extent -1.05,-1.1 1.05,1.1, height 1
